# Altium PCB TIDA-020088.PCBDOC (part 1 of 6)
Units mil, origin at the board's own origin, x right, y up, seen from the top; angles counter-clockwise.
Board outline 7520.69 x 5119.11 mil, 6 copper layers (TOP, GND02, SIG03, SIG04, GND05, BOTTOM), stack 87.024 mil thick; 539 components, 269 nets, 1479 pads, 2085 vias.
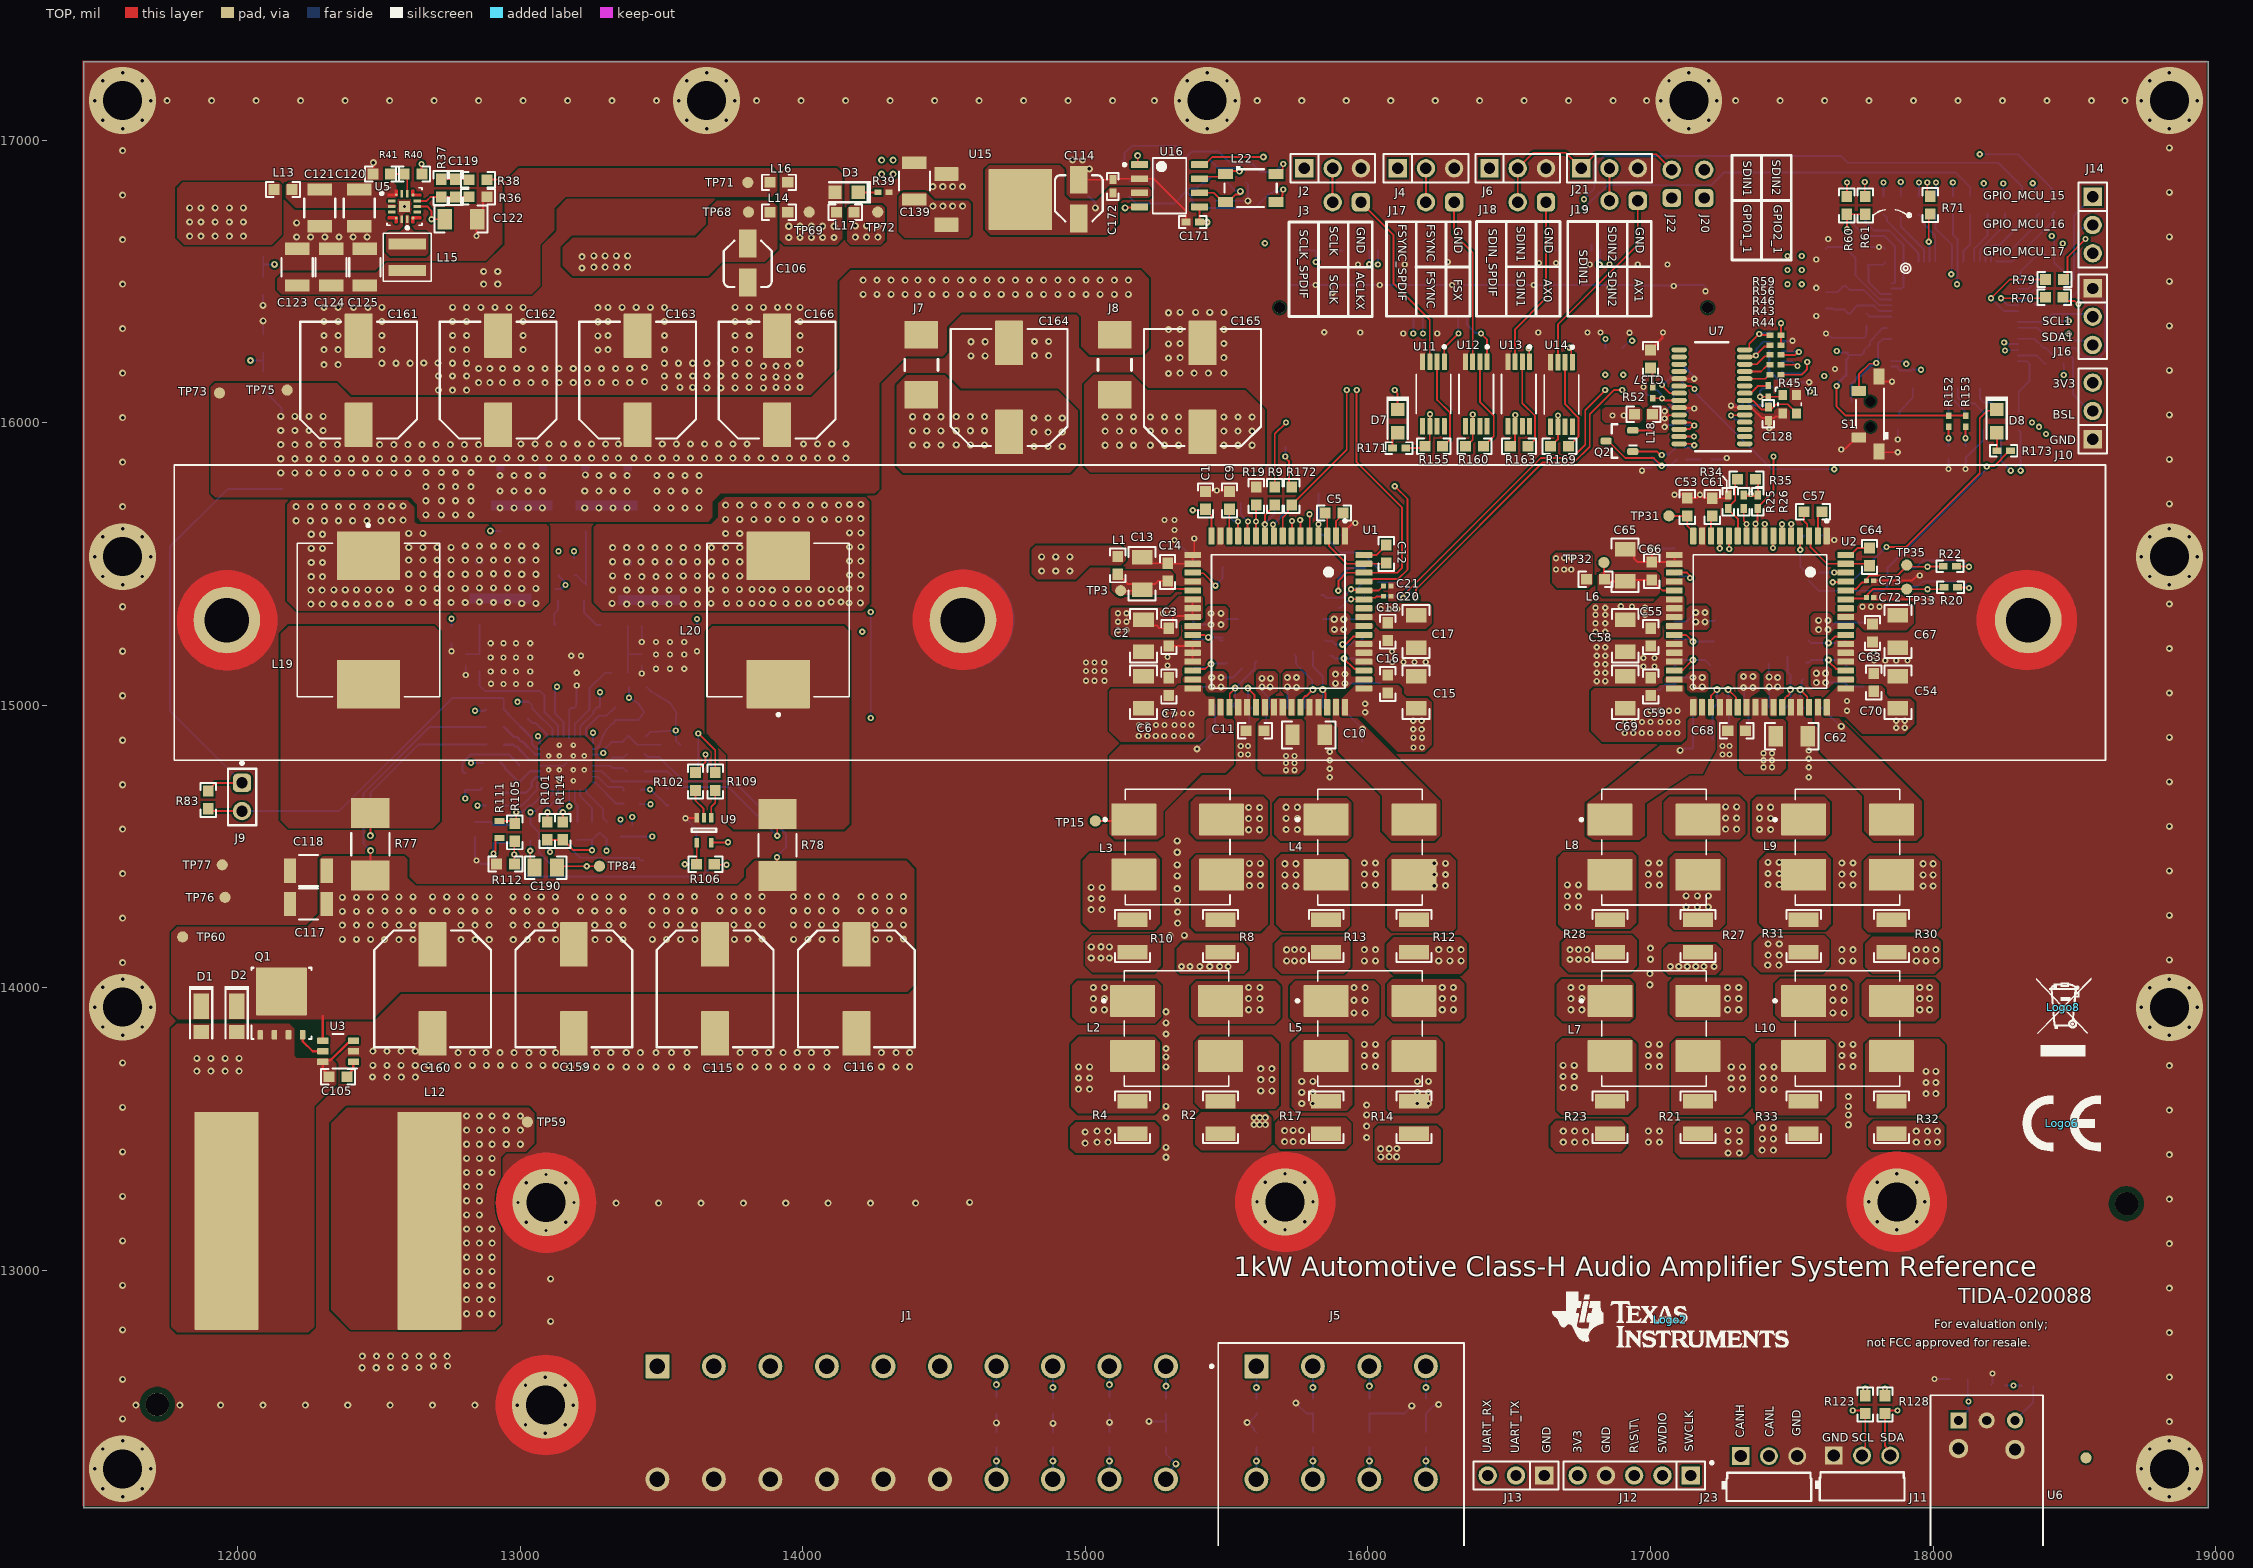
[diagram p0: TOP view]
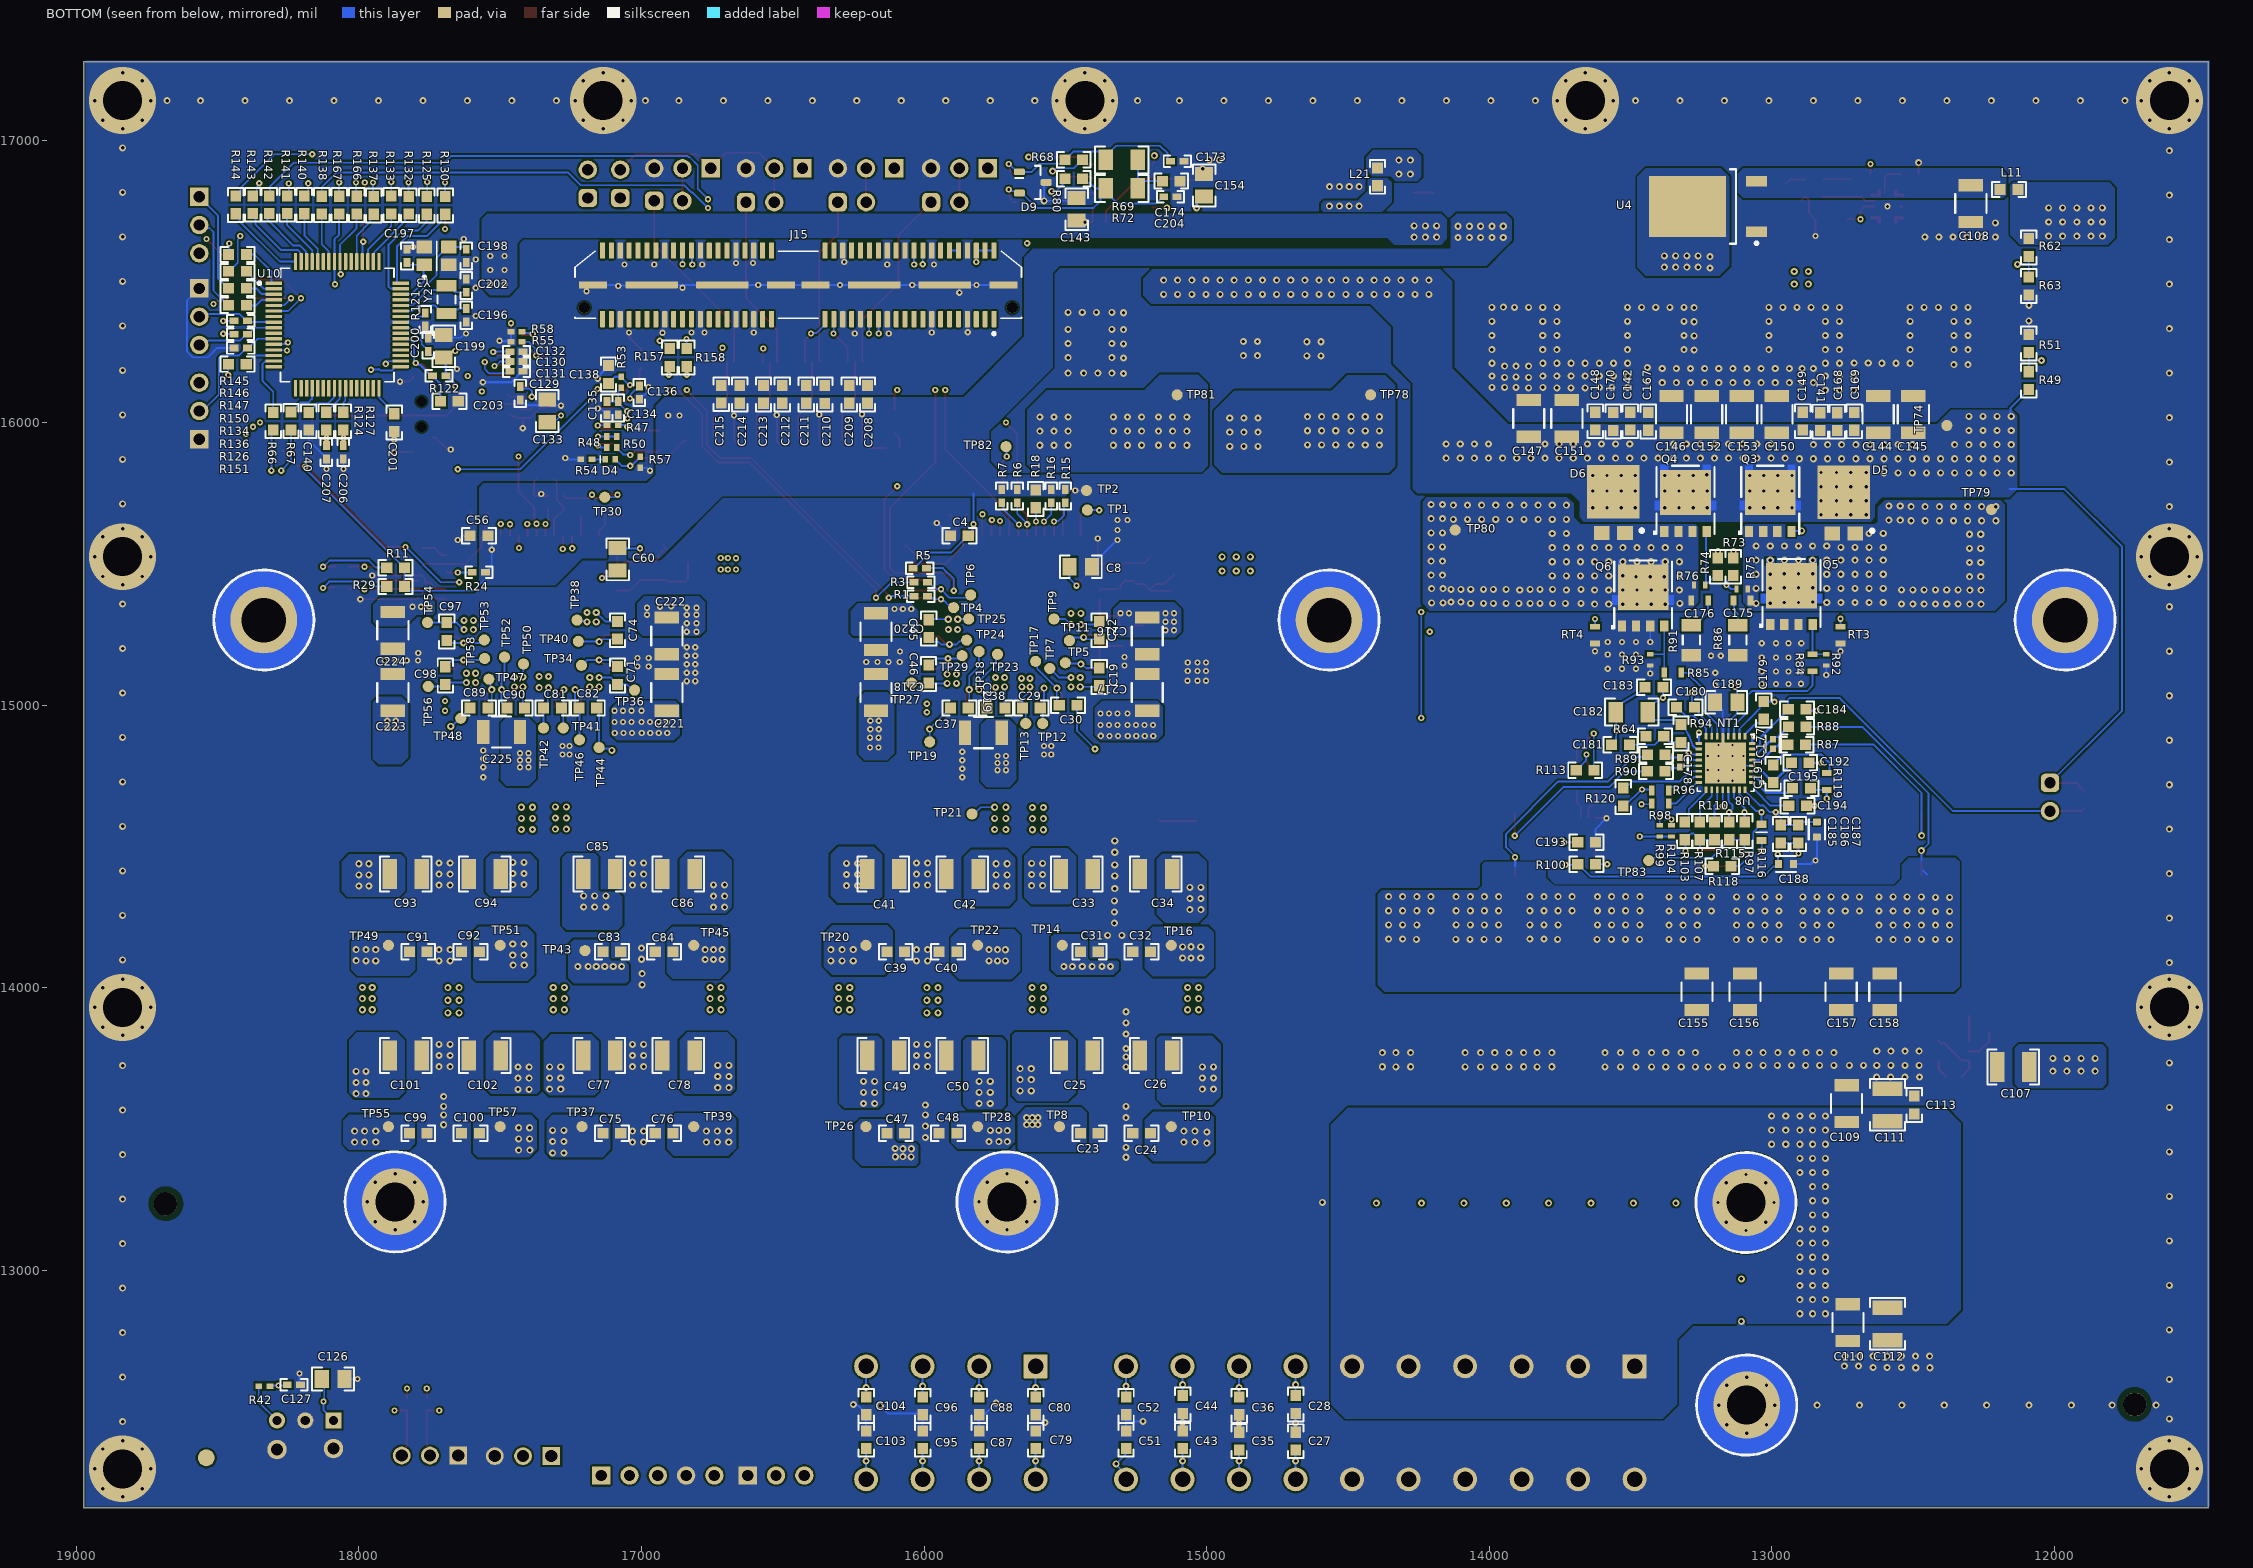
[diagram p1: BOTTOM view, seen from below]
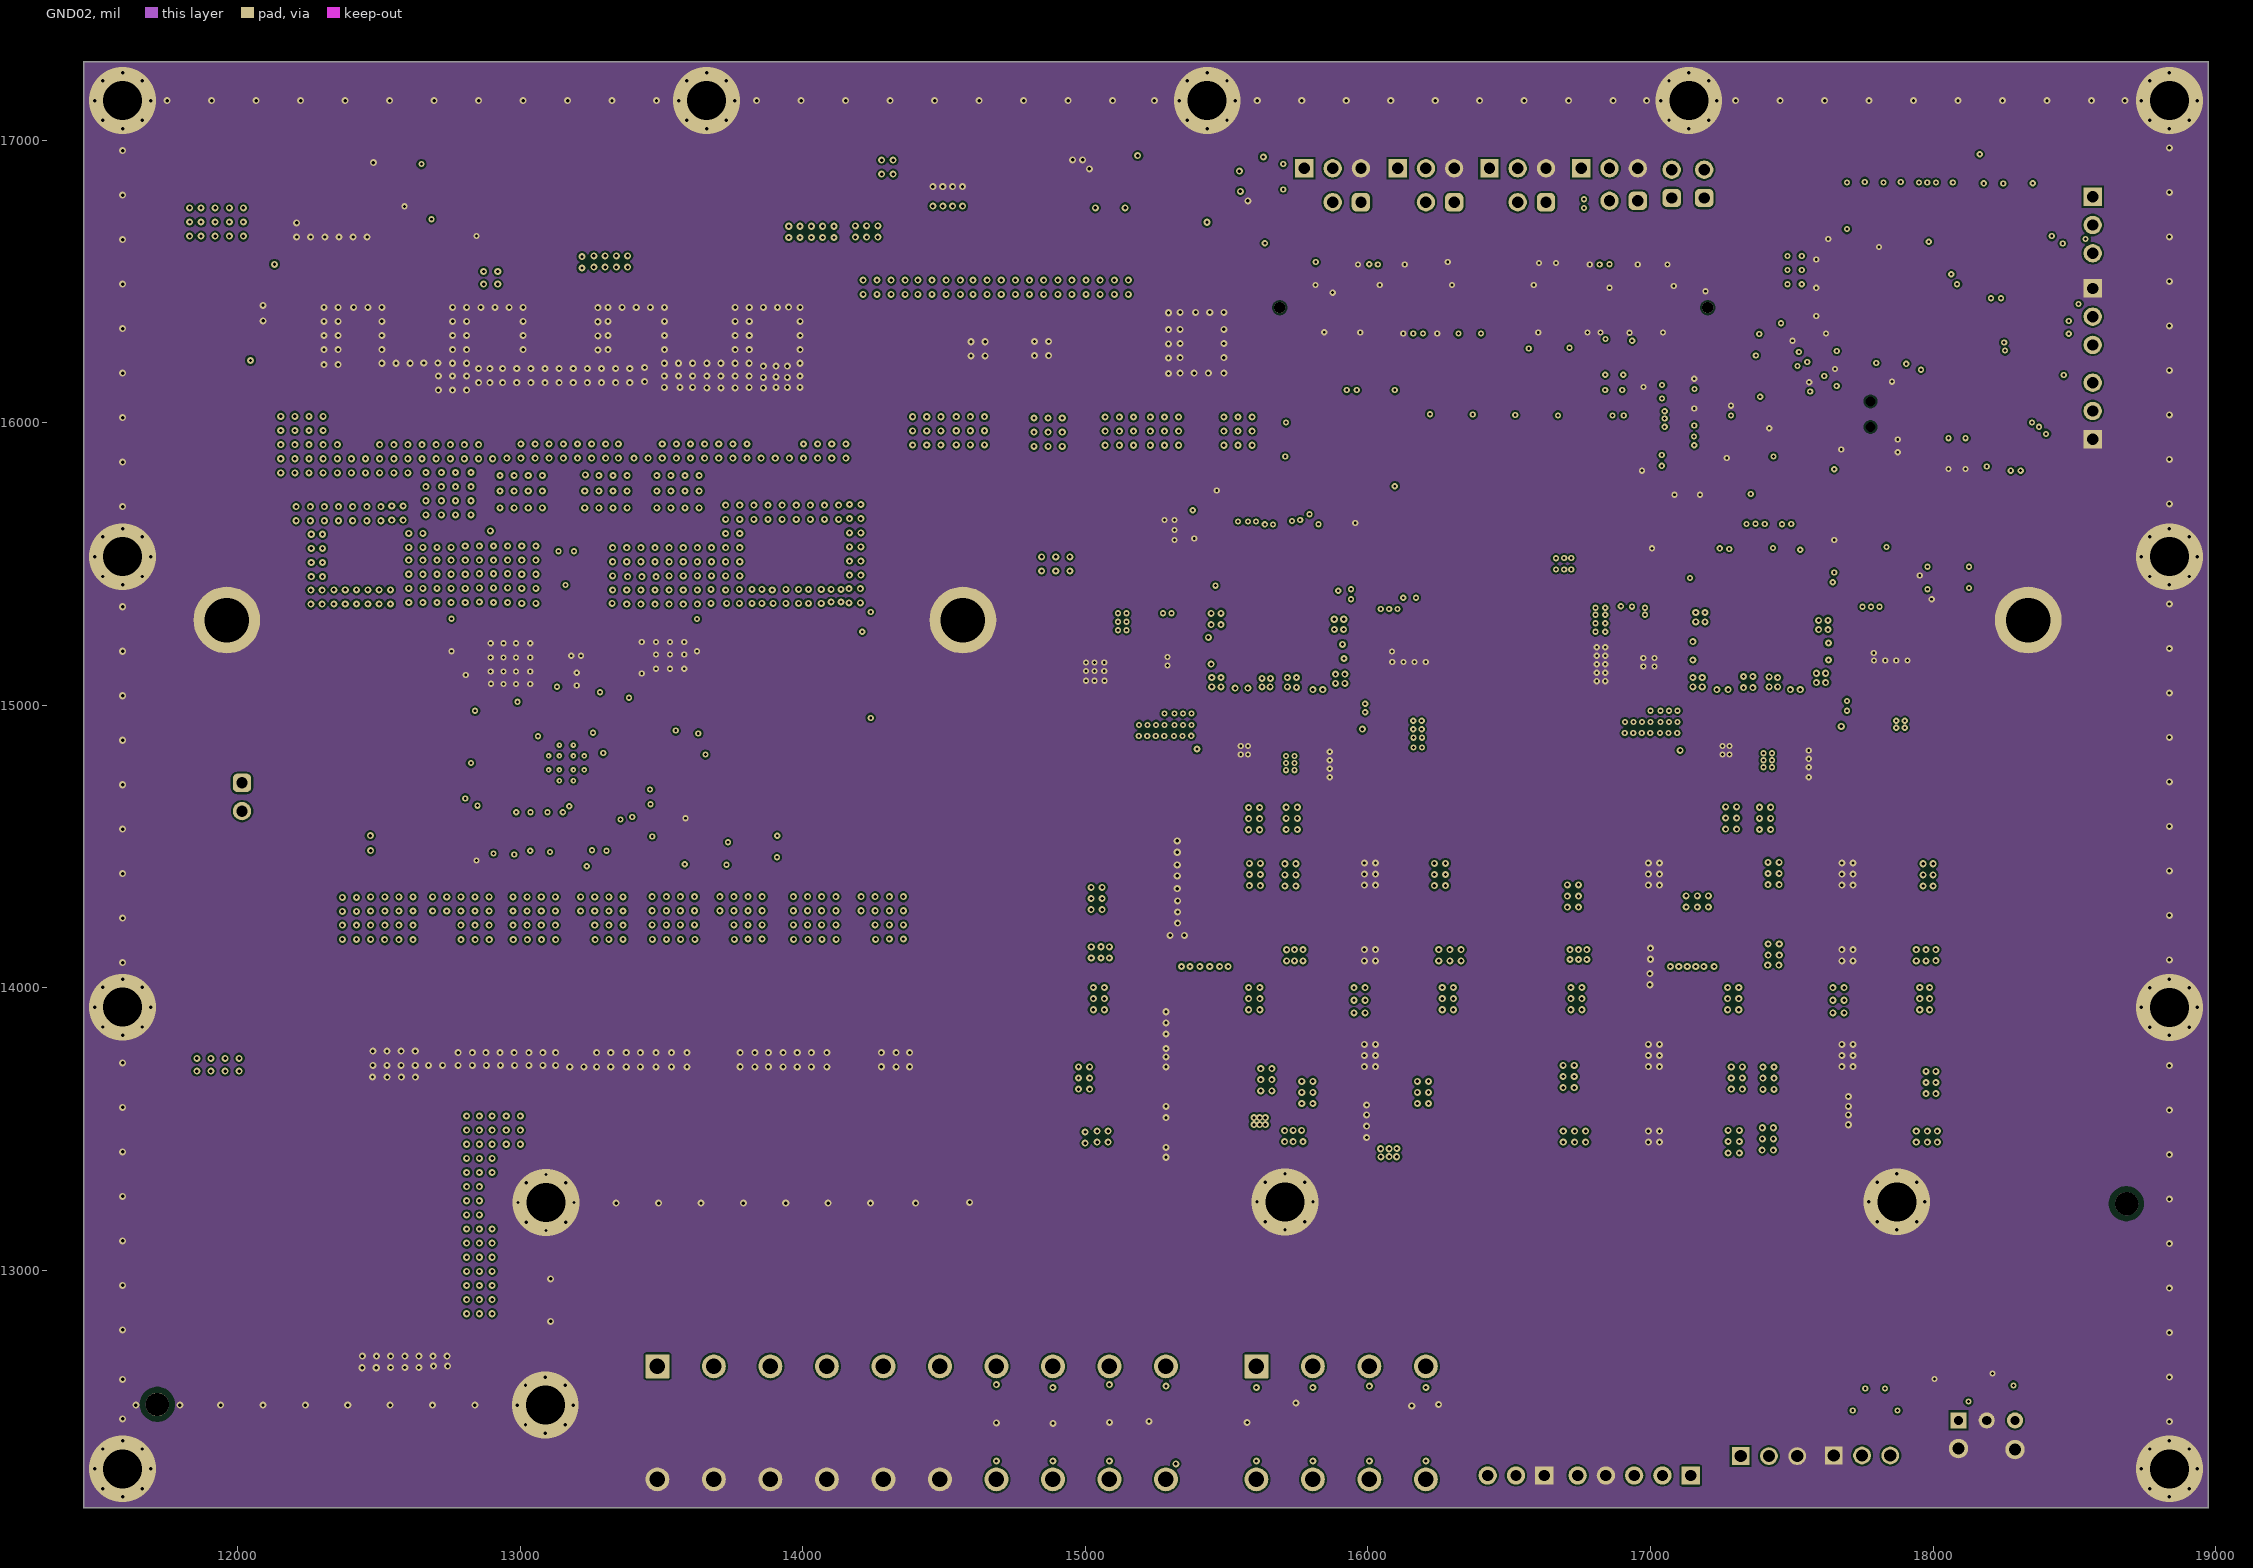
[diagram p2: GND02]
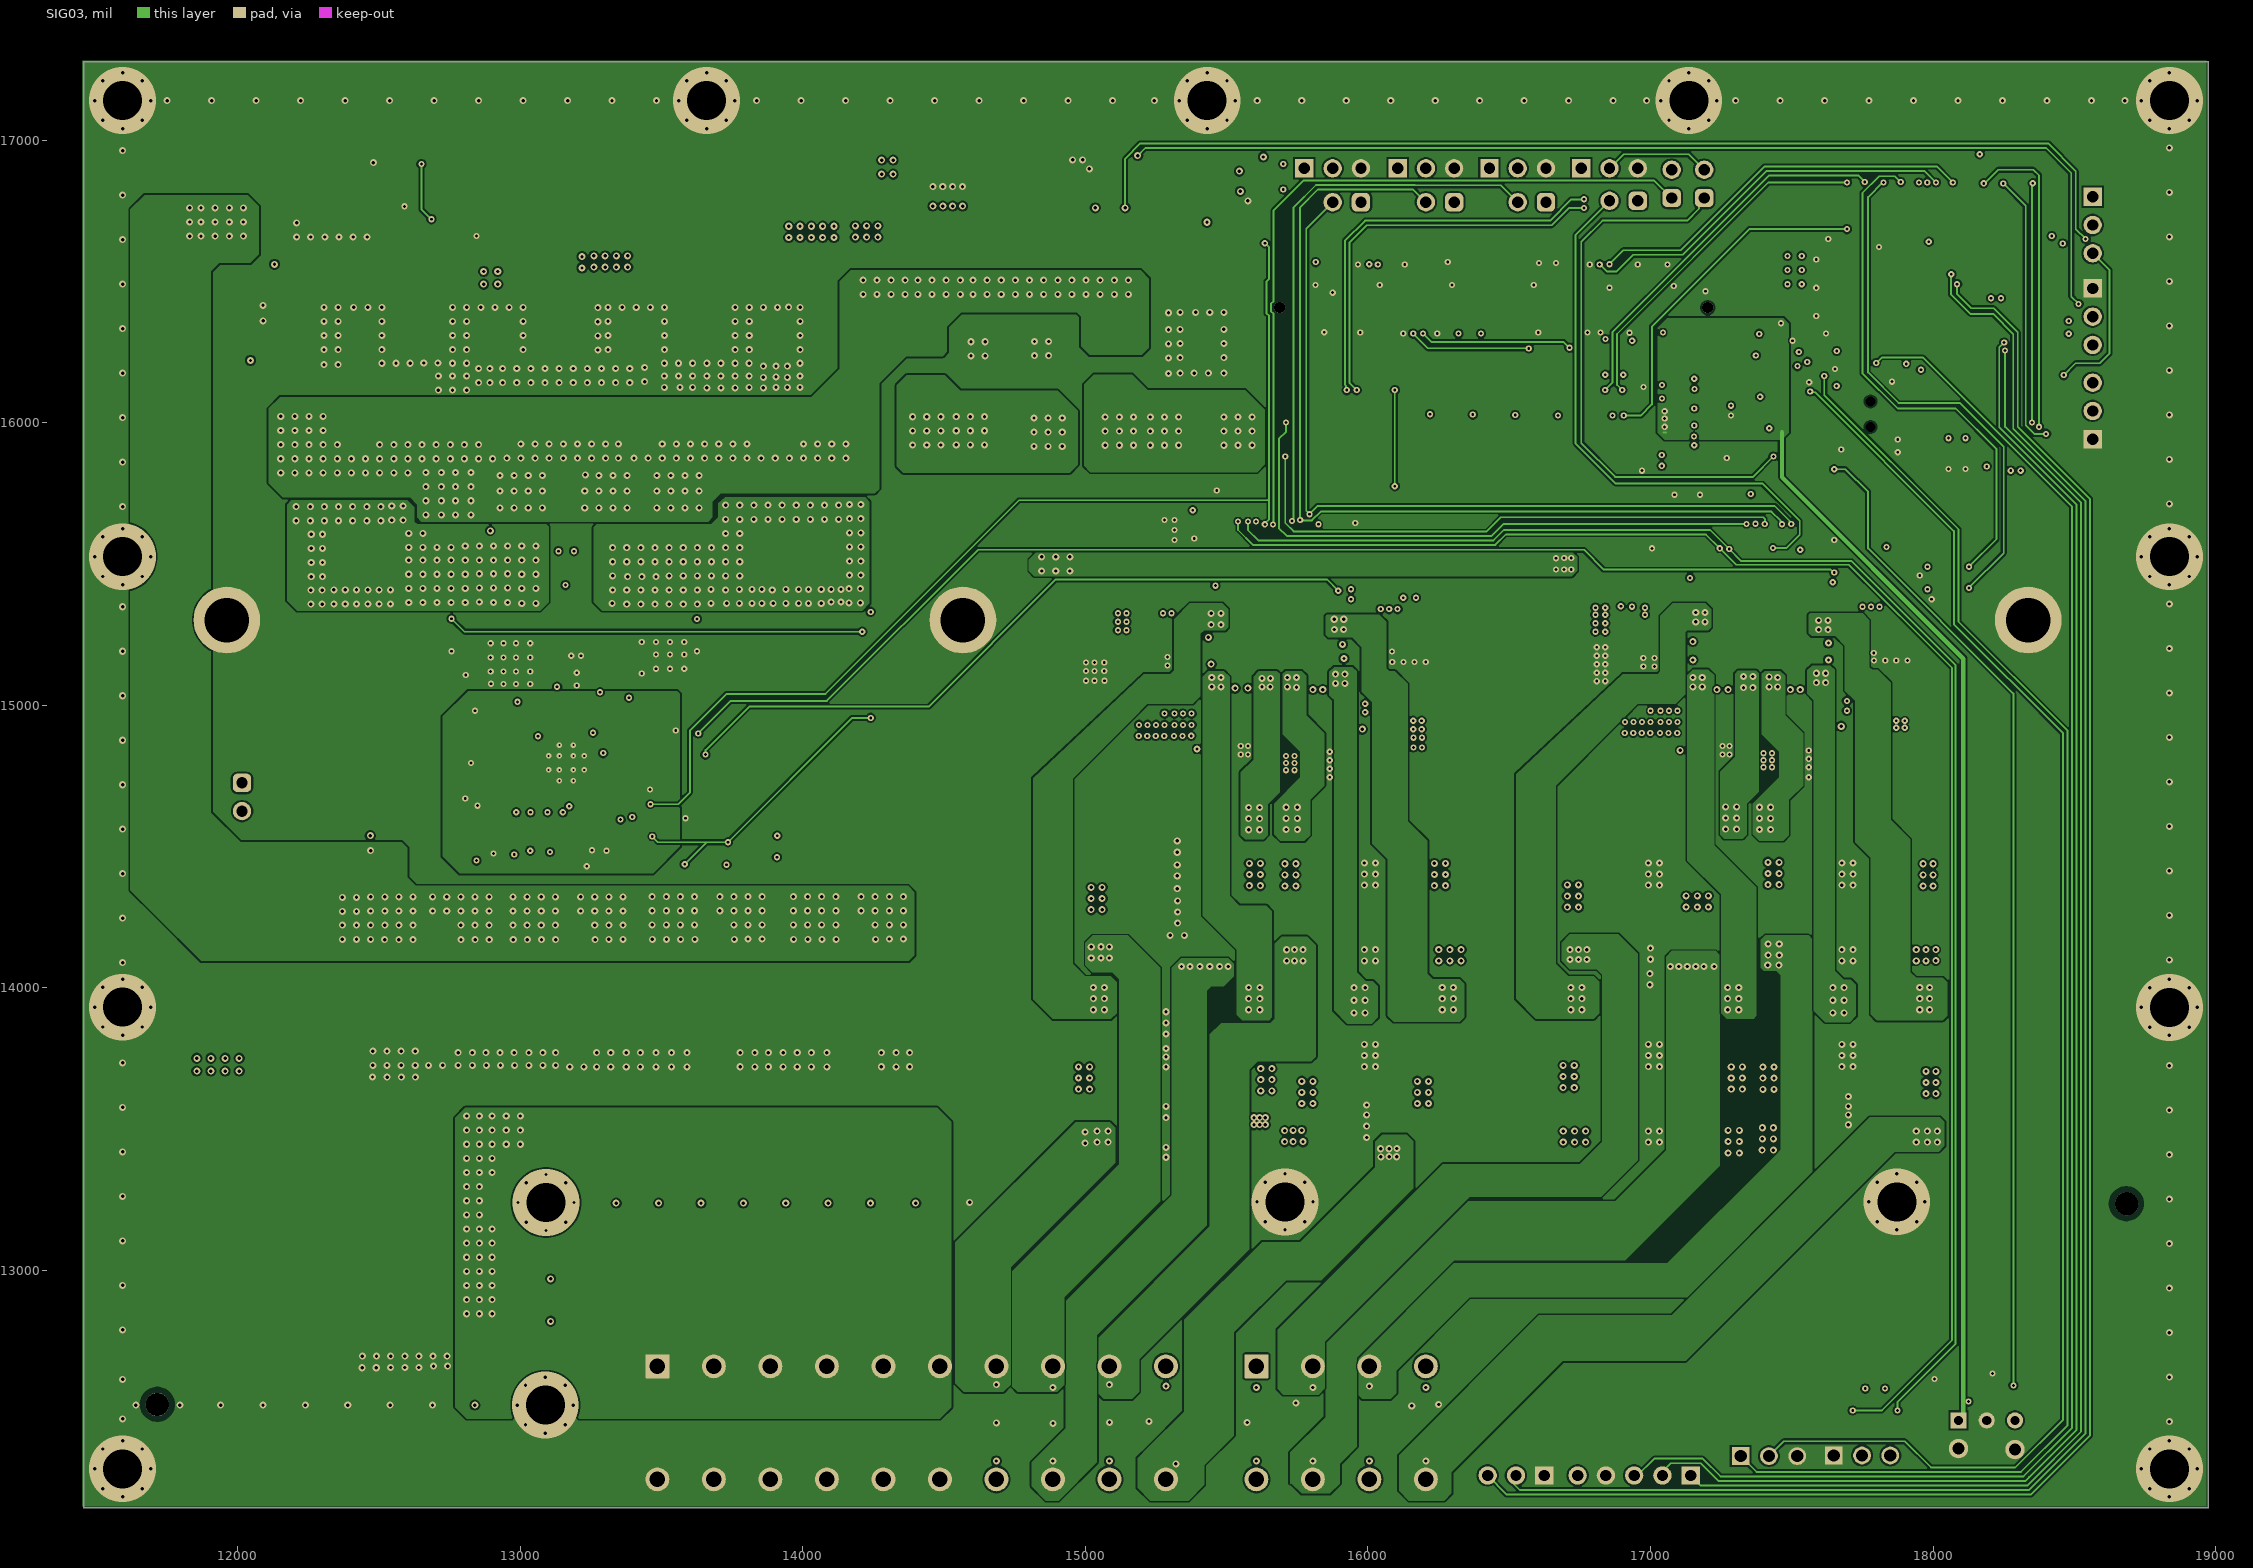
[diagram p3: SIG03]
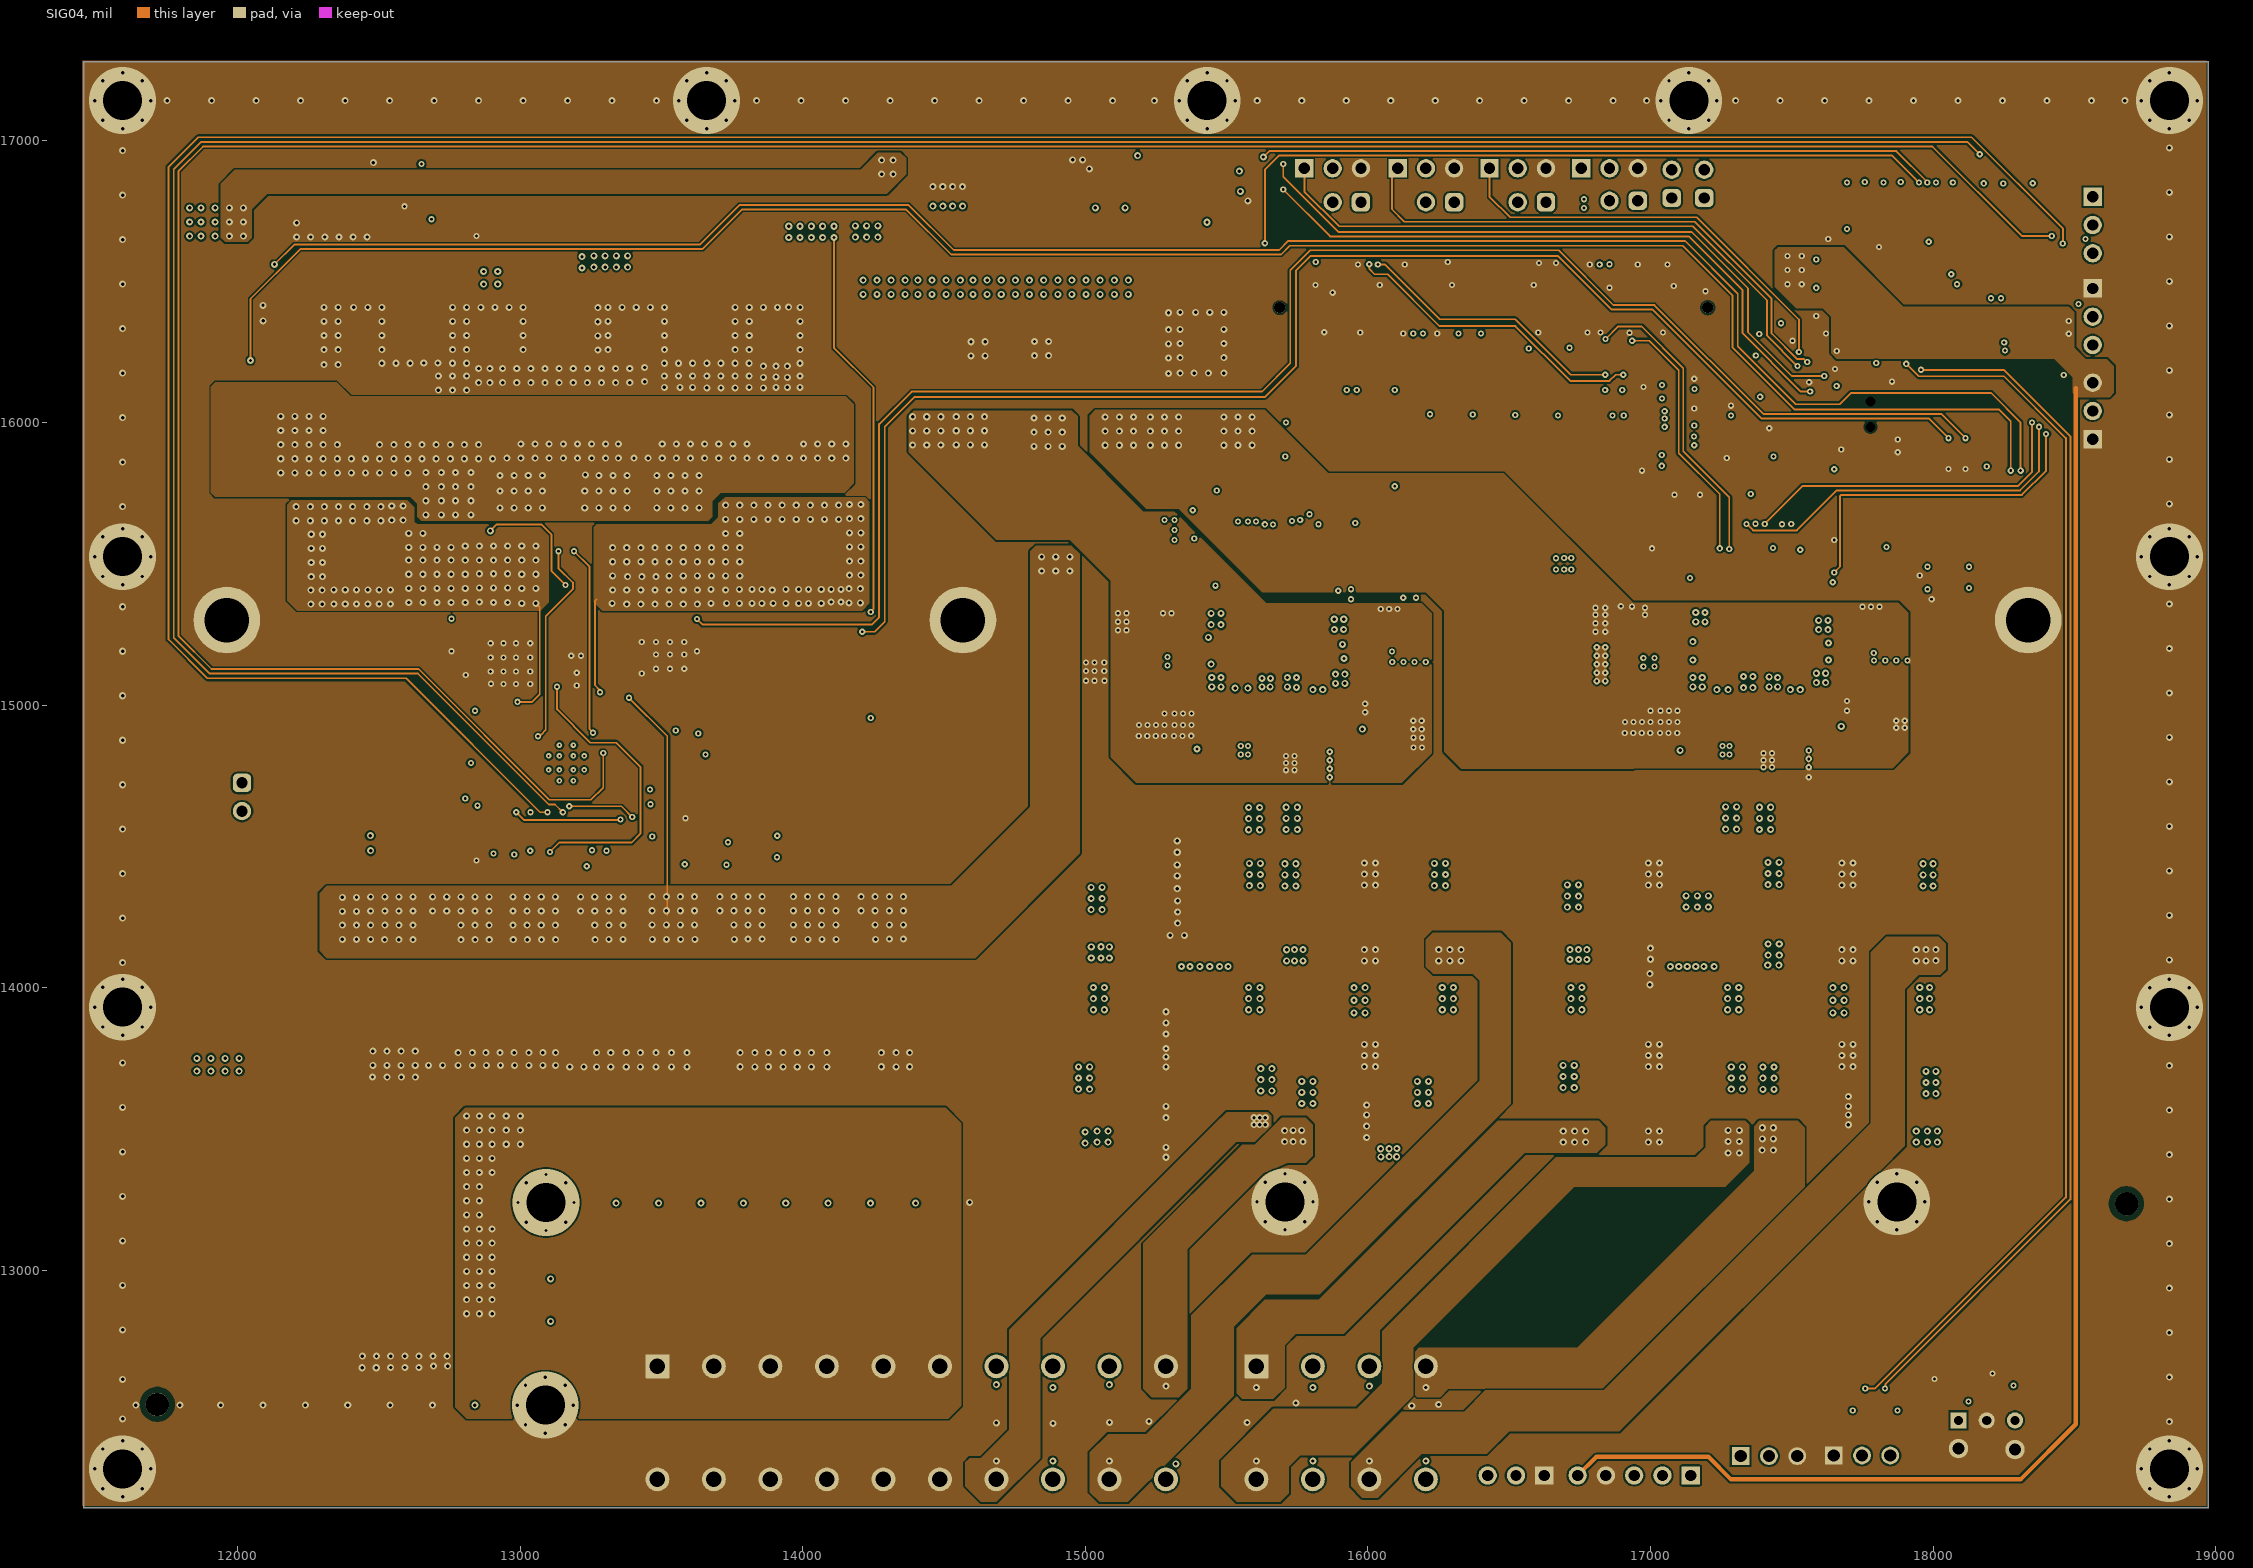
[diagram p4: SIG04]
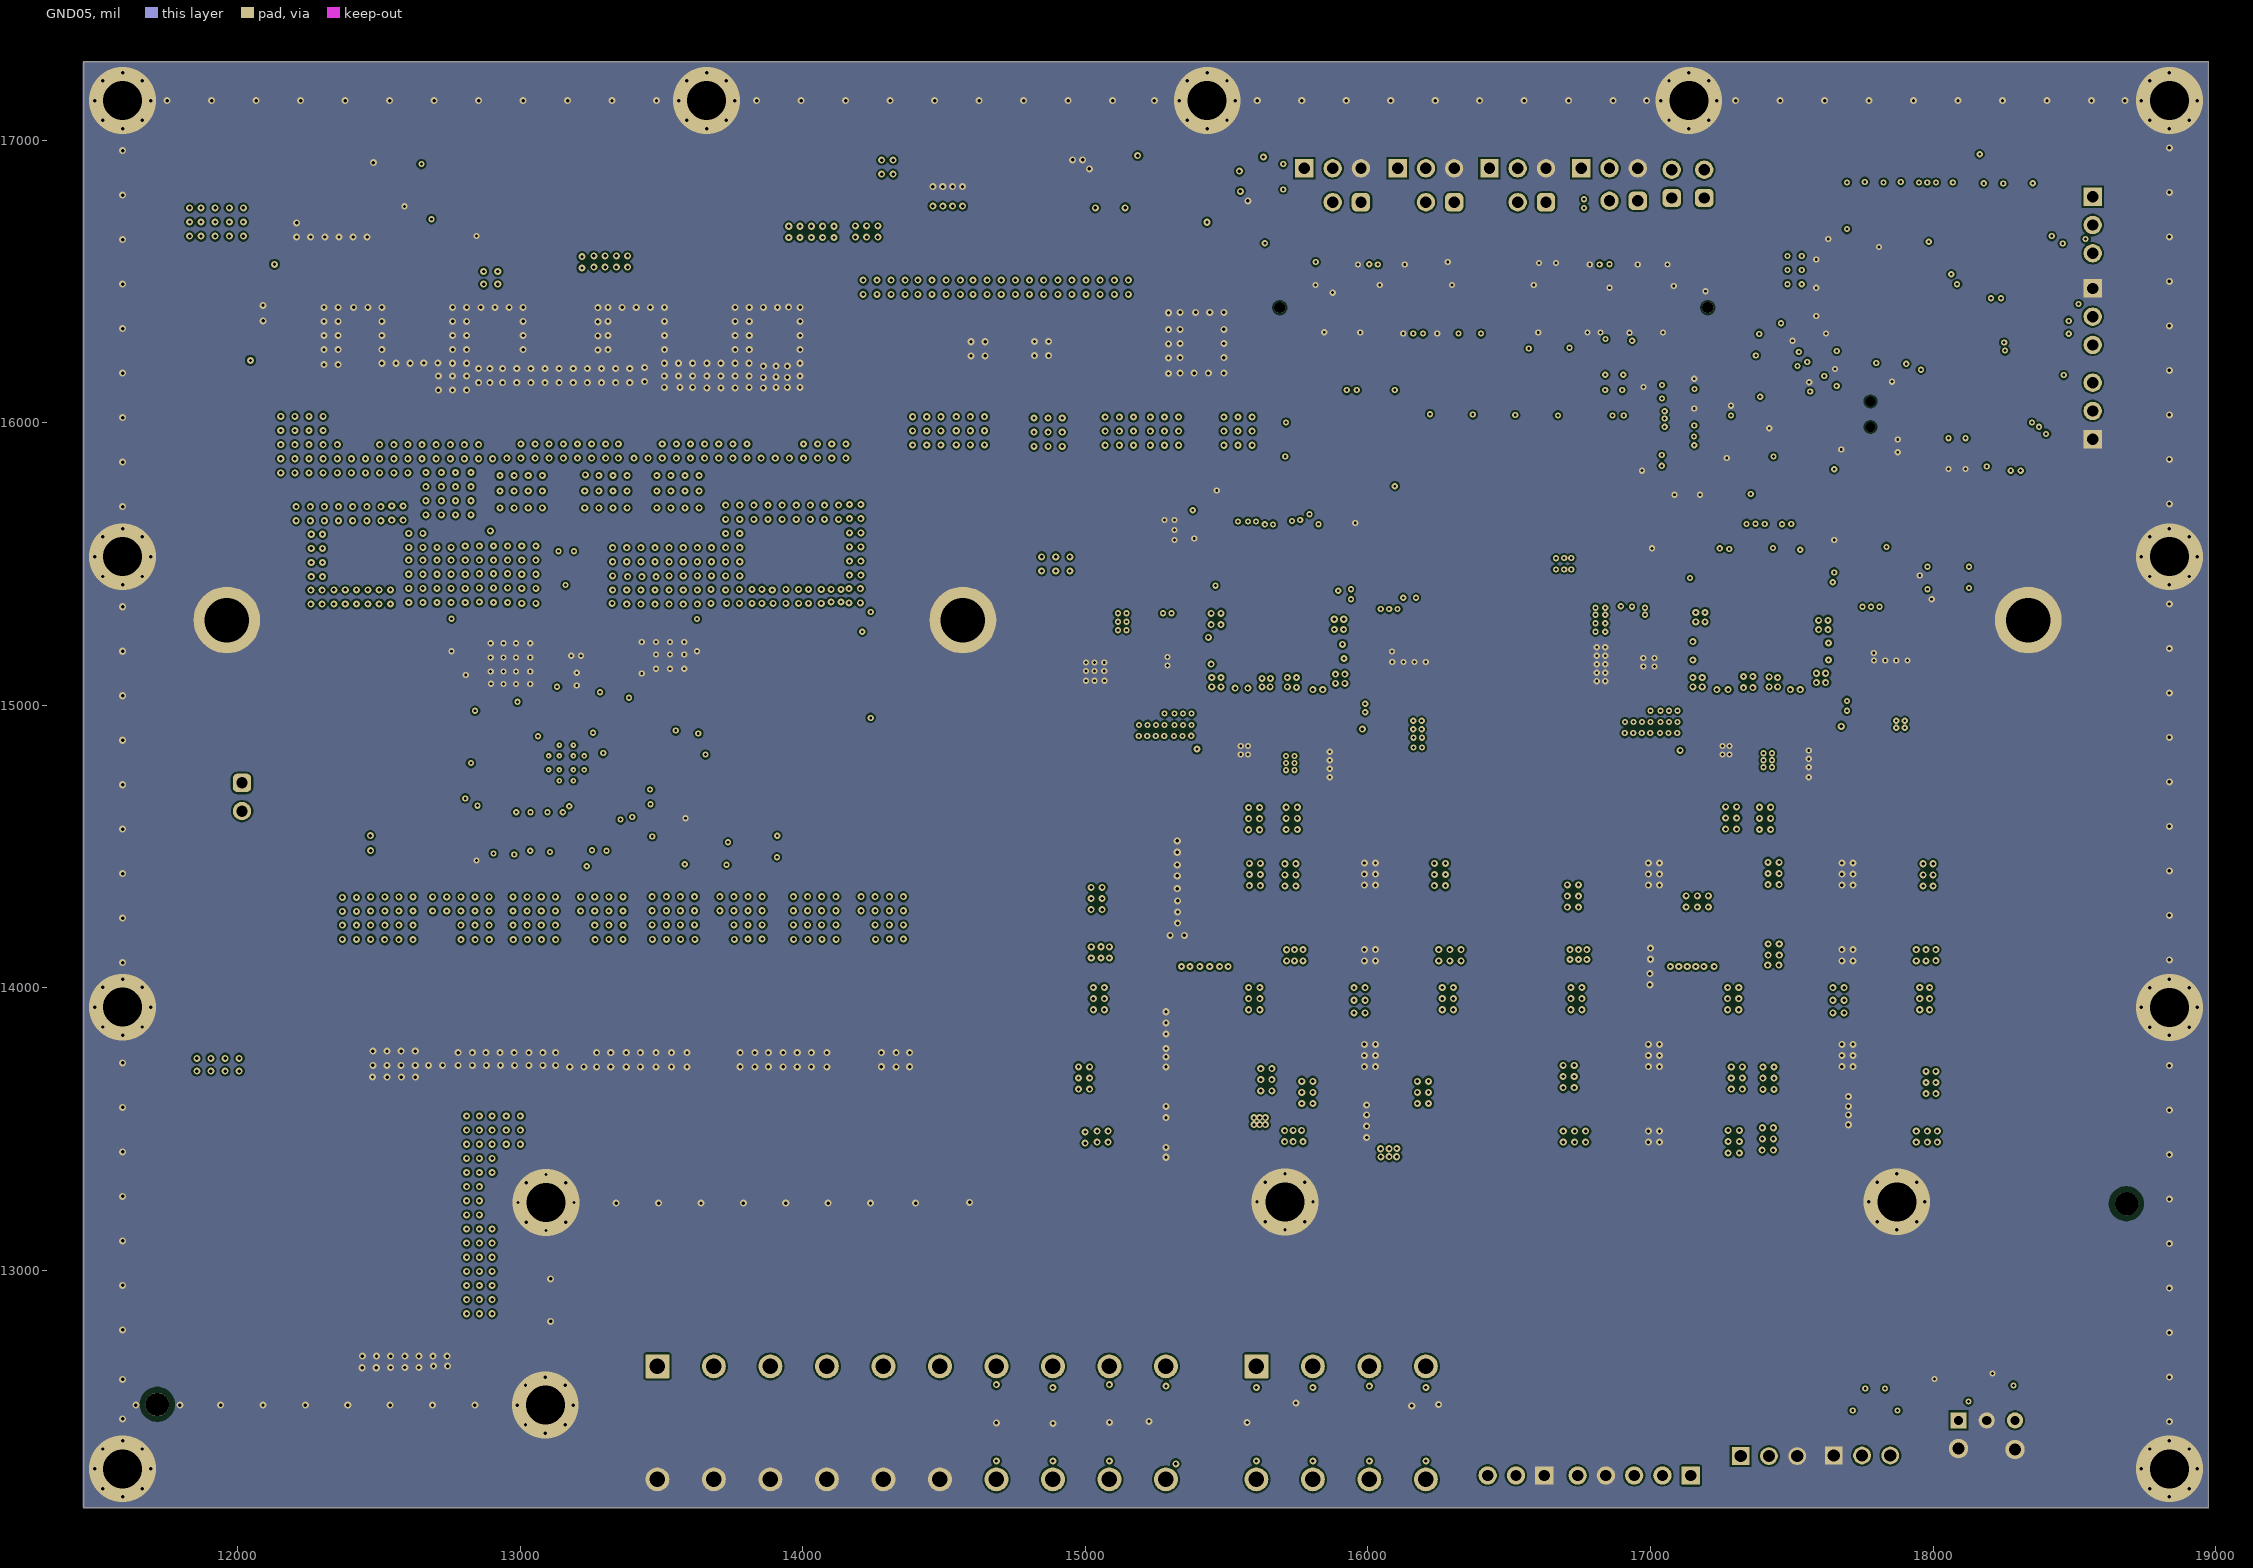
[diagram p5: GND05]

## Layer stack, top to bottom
Top Solder: solder mask 1, SM-002, Dk 4
TOP: signal copper 2.7559
Dielectric1: prepreg 8, FR-4, Dk 4.5
GND02: signal copper 1.378
Dielectric2: core 24, FR-4, Dk 1
SIG03: signal copper 1.378
Dielectric3: prepreg 12, FR-4, Dk 1
SIG04: signal copper 1.378
Dielectric4: core 24, FR-4, Dk 1
GND05: signal copper 1.378
Dielectric5: prepreg 8, FR-4, Dk 1
BOTTOM: signal copper 2.7559
Bottom Solder: solder mask 1, SM-002, Dk 4

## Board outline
11454.06,12159.37 11454.56,12158.87 18974.25,12158.87 18974.75,12159.37 18974.75,17277.48 18974.25,17277.98 11454.56,17277.98 11454.06,17277.48

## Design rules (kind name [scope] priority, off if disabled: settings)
Clearance [All] p1: gap=6.5 ignorepadtopadclearanceinfootprint=FALSE
PlaneConnect [All] p1: planeconnectstyle=Direct reliefexpansion=20 reliefentries=4 reliefconductorwidth=10 reliefairgap=10
PolygonConnect [All] p1: connectstyle=Direct reliefconductorwidth=10 reliefentries=4 polygonreliefangle="90 Angle" airgapwidth=10
RoutingVias [All] p1: holewidth=28 width=50 viastyle="Through Hole" minholewidth=28 minwidth=50 maxholewidth=28 maxwidth=50
SilkToSolderMaskClearance SilkscreenOverComponentPads [IsPad] p1: minsilkscreentomaskgap=10 clearancetoexposedcopper=TRUE
SolderMaskExpansion [All] p1: expansion=4 istentingtop=FALSE
Width [All] p1: maxlimit=100 minlimit=6.5 preferedwidth=8
28 further rules are at their usual default settings.

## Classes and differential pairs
component class Vbat_Input: 0 C105 C106 C107 C108 C109 C110 C111 C112 C113 C114 C115 C116 C117 C118 C119 C120 C121 C122 C123 C124 C125 C139 D1 D2 D3 L11 L12 L13 L14 L15 L16 L17 L21 Q1 R36 R37 R38 R39 R40 R41 TP59 TP60 TP68 TP69 TP71 TP72 U3 U4 U5 U15
component class TAS6684_2: C53 C54 C55 C56 C57 C58 C59 C60 C61 C62 C63 C64 C65 C66 C67 C68 C69 C70 C71 C72 C73 C74 C75 C76 C77 C78 C79 C80 C81 C82 C83 C84 C85 C86 C87 C88 C89 C90 C91 C92 C93 C94 C95 C96 C97 C98 C99 C100 C101 C102 C103 C104 D8 J20 L6 L7 L8 L9 L10 R11 R20 R21 R22 R23 R24 R25 R26 R27 R28 R29 R30 R31 R32 R33 R34 R35 R173 TP30 TP31 TP32 TP33 TP34 TP35 TP36 TP37 TP38 TP39 TP40 TP41 TP42 TP43 TP44 TP45 TP46 TP47 TP48 TP49 TP50 TP51 TP52 TP53 TP54 TP55 TP56 TP57 TP58 U2
component class TAS6684_1: C1 C2 C3 C4 C5 C6 C7 C8 C9 C10 C11 C12 C13 C14 C15 C16 C17 C18 C19 C20 C21 C22 C23 C24 C25 C26 C27 C28 C29 C30 C31 C32 C33 C34 C35 C36 C37 C38 C39 C40 C41 C42 C43 C44 C45 C46 C47 C48 C49 C50 C51 C52 D7 J22 L1 L2 L3 L4 L5 R1 R2 R3 R4 R5 R6 R7 R8 R9 R10 R12 R13 R14 R15 R16 R17 R18 R19 R60 R61 R171 R172 TP1 TP2 TP3 TP4 TP5 TP6 TP7 TP8 TP9 TP10 TP11 TP12 TP13 TP14 TP15 TP16 TP17 TP18 TP19 TP20 TP21 TP22 TP23 TP24 TP25 TP26 TP27 TP28 TP29 TP82 U1
component class "SPDIF and Interface": C126 C127 C128 C129 C130 C131 C132 C133 C134 C135 C136 C137 C138 D4 J1 J2 J4 J5 J6 J21 L18 Logo8 Q2 R42 R43 R44 R45 R46 R47 R48 R50 R52 R53 R54 R55 R56 R57 R58 R59 U6 U7 Y1
component class MCU-MSPM0G3519SPZR: C140 C143 C154 C171 C172 C173 C174 C196 C197 C198 C199 C200 C201 C202 C203 C204 C206 C207 D9 J10 J11 J12 J13 J14 J16 J23 L22 R66 R67 R68 R69 R70 R71 R72 R79 R80 R121 R122 R123 R124 R125 R126 R127 R128 R130 R132 R133 R134 R136 R137 R138 R140 R141 R142 R143 R144 R145 R146 R147 R150 R151 R152 R153 RT3 RT4 S1 U10 U16 Y2 Y3
component class LM5125: C141 C142 C144 C145 C146 C147 C148 C149 C150 C151 C152 C153 C155 C156 C157 C158 C159 C160 C161 C162 C163 C164 C165 C166 C167 C168 C169 C170 C175 C176 C177 C178 C179 C180 C181 C182 C183 C184 C185 C186 C187 C188 C189 C190 C191 C192 C193 C194 C195 C216 C217 C218 C219 C220 C221 C222 C223 C224 C225 D5 D6 J7 J8 J9 L19 L20 NT1 Q3 Q4 Q5 Q6 R49 R51 R62 R63 R64 R73 R74 R75 R76 R77 R78 R83 R84 R85 R86 R87 R88 R89 R90 R91 R92 R93 R94 R96 R97 R98 R99 R100 R101 R102 R103 R104 R105 R106 R107 R109 R110 R111 R112 R113 R114 R115 R116 R118 R119 R120 TP73 TP74 TP75 TP76 TP77 TP78 TP79 TP80 TP81 TP83 TP84 U8 U9
component class Interface_SEM: C208 C209 C210 C211 C212 C213 C214 C215 J3 J15 J17 J18 J19 R155 R157 R158 R160 R163 R166 R167 R169 U11 U12 U13 U14
component class Hardware: !PCB1

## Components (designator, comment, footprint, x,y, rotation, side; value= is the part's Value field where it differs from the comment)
C1 "GCM188R71E105KA64D" 0603 15425,15725 r270 top value=1uF
C2 "GCJ31CR72A105KA01K" 1206 15205.63,15245.64 r270 top value=1uF
C3 "GCJ188R72A104KA01D" 0603 15295.63,15240.64 r90 top value=0.1uF
C4 "GCM188R71E105KA64D" 0603 15875,15600 r180 bottom value=1uF
C5 "GCM188R71E105KA64D" 0603 15880,15680 r0 top value=1uF
C6 "GCJ31CR72A105KA01K" 1206 15205.63,15045.62 r90 top value=1uF
C7 "GCJ188R72A104KA01D" 0603 15295.63,15065.64 r90 top value=0.1uF
C8 "GCM21BR71E225KA73L" 0805_HV 15445,15490 r180 bottom value=2.2uF
C9 "GCM188R71E105KA64D" 0603 15510,15725 r270 top value=1uF
C10 "GCJ31CR72A105KA01K" 1206 15790,14895 r0 top value=1uF
C11 "GCJ188R72A104KA01D" 0603 15600,14910 r180 top value=0.1uF
C12 "GCM188R71E105KA64D" 0603 16065,15535 r90 top value=1uF
C13 "GCJ31CR72A105KA01K" 1206 15200.63,15465.62 r90 top value=1uF
C14 "GCJ188R72A104KA01D" 0603 15290.63,15470.64 r90 top value=0.1uF
C15 "GCJ31CR72A105KA01K" 1206 16170.63,15045.62 r90 top value=1uF
C16 "GCJ188R72A104KA01D" 0603 16070,15075 r90 top value=0.1uF
C17 "GCJ31CR72A105KA01K" 1206 16170.63,15260.64 r270 top value=1uF
C18 "GCJ188R72A104KA01D" 0603 16070,15260 r270 top value=0.1uF
C19 "GCM188R71H224KA64D" 0603 15380,15100 r270 bottom value=0.22uF
C20 "GCM033R71E101KA03D" 0201_033 16067.99,15385 r0 top value=100pF
C21 "GCM033R71E101KA03D" 0201_033 16068.08,15421.8 r0 top value=100pF
C22 "GCM188R71H224KA64D" 0603 15380,15265 r270 bottom value=0.22uF
C23 "DNP" 0603 15415,13485 r180 bottom value=0.22uF
C24 "DNP" 0603 15230,13485 r0 bottom value=0.22uF
C25 "CGA6N3X7R2A225K230AB" 1210_250 15459.37,13760 r180 bottom value=2.2uF
C26 "CGA6N3X7R2A225K230AB" 1210_250 15179.37,13760 r0 bottom value=2.2uF
C27 "CGA3E2X7R2A103K080AA" 0603 14685,12395 r90 bottom value=0.01uF
C28 "CGA3E2X7R2A103K080AA" 0603 14685,12525 r270 bottom value=0.01uF
C29 "GCM188R71H224KA64D" 0603 15620,14990 r0 bottom value=0.22uF
C30 "GCM188R71H224KA64D" 0603 15490,15000 r0 bottom value=0.22uF
C31 "DNP" 0603 15415,14127 r180 bottom value=0.22uF
C32 "DNP" 0603 15230,14127 r0 bottom value=0.22uF
C33 "CGA6N3X7R2A225K230AB" 1210_250 15459.37,14402 r180 bottom value=2.2uF
C34 "CGA6N3X7R2A225K230AB" 1210_250 15179.37,14402 r0 bottom value=2.2uF
C35 "CGA3E2X7R2A103K080AA" 0603 14885,12395 r90 bottom value=0.01uF
C36 "CGA3E2X7R2A103K080AA" 0603 14885,12520 r270 bottom value=0.01uF
C37 "GCM188R71H224KA64D" 0603 15875,14990 r0 bottom value=0.22uF
C38 "GCM188R71H224KA64D" 0603 15745,14990 r0 bottom value=0.22uF
C39 "DNP" 0603 16100,14127 r180 bottom value=0.22uF
C40 "DNP" 0603 15915,14127 r0 bottom value=0.22uF
C41 "CGA6N3X7R2A225K230AB" 1210_250 16144.37,14402 r180 bottom value=2.2uF
C42 "CGA6N3X7R2A225K230AB" 1210_250 15864.37,14402 r0 bottom value=2.2uF
C43 "CGA3E2X7R2A103K080AA" 0603 15085,12400 r90 bottom value=0.01uF
C44 "CGA3E2X7R2A103K080AA" 0603 15085,12525 r270 bottom value=0.01uF
C45 "GCM188R71H224KA64D" 0603 15983.74,15270.78 r90 bottom value=0.22uF
C46 "GCM188R71H224KA64D" 0603 15984,15110 r90 bottom value=0.22uF
C47 "DNP" 0603 16100,13485 r180 bottom value=0.22uF
C48 "DNP" 0603 15915,13485 r0 bottom value=0.22uF
C49 "CGA6N3X7R2A225K230AB" 1210_250 16144.37,13760 r180 bottom value=2.2uF
C50 "CGA6N3X7R2A225K230AB" 1210_250 15864.37,13760 r0 bottom value=2.2uF
C51 "CGA3E2X7R2A103K080AA" 0603 15285,12400 r90 bottom value=0.01uF
C52 "CGA3E2X7R2A103K080AA" 0603 15285,12520 r270 bottom value=0.01uF
C53 "GCM188R71E105KA64D" 0603 17130,15701.5 r270 top value=1uF
C54 "GCJ31CR72A105KA01K" 1206 17875.63,15045.62 r90 top value=1uF
C55 "GCJ188R72A104KA01D" 0603 17000.63,15240.64 r90 top value=0.1uF
C56 "GCM188R71E105KA64D" 0603 17575,15600 r180 bottom value=1uF
C57 "GCM188R71E105KA64D" 0603 17575,15685 r0 top value=1uF
C58 "GCJ31CR72A105KA01K" 1206 16910.63,15245.64 r270 top value=1uF
C59 "GCJ188R72A104KA01D" 0603 17000.63,15065.64 r90 top value=0.1uF
C60 "GCM21BR71E225KA73L" 0805_HV 17084.37,15516.1 r90 bottom value=2.2uF
C61 "GCM188R71E105KA64D" 0603 17218.97,15700.87 r270 top value=1uF
C62 "GCJ31CR72A105KA01K" 1206 17500,14890 r0 top value=1uF
C63 "GCJ188R72A104KA01D" 0603 17785.63,15255.62 r270 top value=0.1uF
C64 "GCM188R71E105KA64D" 0603 17775,15525 r90 top value=1uF
C65 "GCJ31CR72A105KA01K" 1206 16910,15495 r90 top value=1uF
C66 "GCJ188R72A104KA01D" 0603 17005,15475 r90 top value=0.1uF
C67 "GCJ31CR72A105KA01K" 1206 17875.63,15260.64 r270 top value=1uF
C68 "GCJ188R72A104KA01D" 0603 17305,14910 r180 top value=0.1uF
C69 "GCJ31CR72A105KA01K" 1206 16910.63,15045.62 r90 top value=1uF
C70 "GCJ188R72A104KA01D" 0603 17790.63,15080.64 r90 top value=0.1uF
C71 "GCM188R71H224KA64D" 0603 17085,15105 r270 bottom value=0.22uF
C72 "GCM033R71E101KA03D" 0201_033 17777.01,15380.94 r0 top value=100pF
C73 "GCM033R71E101KA03D" 0201_033 17777.01,15440 r0 top value=100pF
C74 "GCM188R71H224KA64D" 0603 17085,15265 r270 bottom value=0.22uF
C75 "DNP" 0603 17105,13485 r180 bottom value=0.22uF
C76 "DNP" 0603 16920,13485 r0 bottom value=0.22uF
C77 "CGA6N3X7R2A225K230AB" 1210_250 17149.37,13760 r180 bottom value=2.2uF
C78 "CGA6N3X7R2A225K230AB" 1210_250 16869.37,13760 r0 bottom value=2.2uF
C79 "CGA3E2X7R2A103K080AA" 0603 15605,12400 r90 bottom value=0.01uF
C80 "CGA3E2X7R2A103K080AA" 0603 15605,12520 r270 bottom value=0.01uF
C81 "GCM188R71H224KA64D" 0603 17315,14990 r0 bottom value=0.22uF
C82 "GCM188R71H224KA64D" 0603 17190,14990 r0 bottom value=0.22uF
C83 "DNP" 0603 17105,14127 r180 bottom value=0.22uF
C84 "DNP" 0603 16920,14127 r0 bottom value=0.22uF
C85 "CGA6N3X7R2A225K230AB" 1210_250 17149.37,14402 r180 bottom value=2.2uF
C86 "CGA6N3X7R2A225K230AB" 1210_250 16869.37,14402 r0 bottom value=2.2uF
C87 "CGA3E2X7R2A103K080AA" 0603 15805,12400 r90 bottom value=0.01uF
C88 "CGA3E2X7R2A103K080AA" 0603 15805,12520 r270 bottom value=0.01uF
C89 "GCM188R71H224KA64D" 0603 17575,14990 r0 bottom value=0.22uF
C90 "GCM188R71H224KA64D" 0603 17445,14990 r0 bottom value=0.22uF
C91 "DNP" 0603 17790,14127 r180 bottom value=0.22uF
C92 "DNP" 0603 17605,14127 r0 bottom value=0.22uF
C93 "CGA6N3X7R2A225K230AB" 1210_250 17834.37,14402 r180 bottom value=2.2uF
C94 "CGA6N3X7R2A225K230AB" 1210_250 17554.37,14402 r0 bottom value=2.2uF
C95 "CGA3E2X7R2A103K080AA" 0603 16005,12400 r90 bottom value=0.01uF
C96 "CGA3E2X7R2A103K080AA" 0603 16005,12520 r270 bottom value=0.01uF
C97 "GCM188R71H224KA64D" 0603 17688.79,15260.66 r90 bottom value=0.22uF
C98 "GCM188R71H224KA64D" 0603 17693.83,15104.36 r90 bottom value=0.22uF
C99 "DNP" 0603 17790,13485 r180 bottom value=0.22uF
C100 "DNP" 0603 17605,13485 r0 bottom value=0.22uF
C101 "CGA6N3X7R2A225K230AB" 1210_250 17834.37,13760 r180 bottom value=2.2uF
C102 "CGA6N3X7R2A225K230AB" 1210_250 17554.37,13760 r0 bottom value=2.2uF
C103 "CGA3E2X7R2A103K080AA" 0603 16205,12400 r90 bottom value=0.01uF
C104 "CGA3E2X7R2A103K080AA" 0603 16205,12520 r270 bottom value=0.01uF
C105 "GCM188R71E105KA64D" 0603 12355,13685 r0 top value=1uF
C106 "EEE-FT1C470AR" Panasonic_B 13805,16565 r270 top value=47uF
C107 "GCM32ER71H475KA55L" 1210_270 12145,13720 r0 bottom value=4.7uF
C108 "UMK325AB7106KMHT" 1210_280 12295,16775 r270 bottom value=10uF
C109 "UMK325AB7106KMHT" 1210_280 12735,13590 r90 bottom value=10uF
C110 "UMK325AB7106KMHT" 1210_280 12730,12815 r270 bottom value=10uF
C111 "GCM32ER71H475KA55L" 1210_270 12590,13585 r90 bottom value=4.7uF
C112 "GCM32ER71H475KA55L" 1210_270 12590,12810 r270 bottom value=4.7uF
C113 "GCJ188R72A104KA01D" 0603 12495,13585 r90 bottom value=0.1uF
C114 "EEE-FT1C470AR" Panasonic_B 14976.56,16790.92 r90 top value=47uF
C115 "UCM1H331MNL1GS" Nichicon_1000x1000 13689.37,13995.63 r270 top value=330uF
C116 "UCM1H331MNL1GS" Nichicon_1000x1000 14189.37,13995.63 r270 top value=330uF
C117 "UMK325AB7106KMHT" 1210_280 12250,14296.26 r180 top value=10uF
C118 "UMK325AB7106KMHT" 1210_280 12250,14414.3 r180 top value=10uF
C119 "GCM1885C2A100JA16D" 0603 12770,16830 r90 top value=10pF
C120 "UMK325AB7106KMHT" 1210_280 12430,16760 r270 top value=10uF
C121 "UMK325AB7106KMHT" 1210_280 12290,16760 r270 top value=10uF
C122 "GCJ31CR72A105KA01K" 1206 12790,16720 r0 top value=1uF
C123 "CGA6P1X7R1C226M250AC" 1210_280 12210,16550 r90 top value=22uF
C124 "CGA6P1X7R1C226M250AC" 1210_280 12330,16550 r90 top value=22uF
C125 "CGA6P1X7R1C226M250AC" 1210_280 12450,16550 r90 top value=22uF
C126 "C0805C106J8RACAUTO" 0805_HV 18091.52,12615 r180 bottom value=10uF
C127 "GCM1555C1H100JA16D" 0402 18230,12595 r180 bottom value=10pF
C128 "GCQ1555C1H200JB01D" 0402 17417.28,16031.37 r270 top value=20pF
C129 "GCQ1555C1H200JB01D" 0402 17428.61,16103.74 r270 bottom value=20pF
C130 "GCM1555C1H100JA16D" 0402 17442.28,16216.37 r180 bottom value=10pF
C131 "GCM1555C1H100JA16D" 0402 17442.28,16181.37 r180 bottom value=10pF
C132 "GCM1555C1H100JA16D" 0402 17442.28,16251.37 r180 bottom value=10pF
C133 "C0805C106J8RACAUTO" 0805_HV 17333.7,16041.37 r90 bottom value=10uF
C134 "GCM155R71C104JA55D" 0402 17082.28,16051.37 r90 bottom value=0.1uF
C135 "GCM155R71C104JA55D" 0402 17122.28,16051.37 r90 bottom value=0.1uF
C136 "GCM155R71H472KA37D" 0402 17007.28,16106.37 r270 bottom value=4700pF
C137 "CGA3E2X7R1H683K080AA" 0603 17000,16225 r90 top value=0.068uF
C138 "GCM188R71E105KA64D" 0603 17116.69,16170.26 r90 bottom value=1uF
C139 "UMK325AB7106KMHT" 1210_280 14395,16855 r90 top value=10uF
C140 "GCM188R71E105KA64D" 0603 18177.66,16004.89 r90 bottom value=1uF
C141 "GCJ188R72A104KA01D" 0603 12828.26,16003.23 r90 bottom value=0.1uF
C142 "GCJ188R72A104KA01D" 0603 13499.98,16005.03 r90 bottom value=0.1uF
C143 "C0805C106J8RACAUTO" 0805_HV 15460,16755 r270 bottom value=10uF
C144 "UMK325AB7106KMHT" 1210_280 12623,16029.38 r90 bottom value=10uF
C145 "UMK325AB7106KMHT" 1210_280 12498.4,16029.38 r90 bottom value=10uF
C146 "UMK325AB7106KMHT" 1210_280 13354.52,16029.38 r90 bottom value=10uF
C147 "UMK325AB7106KMHT" 1210_280 13859.66,16015 r90 bottom value=10uF
C148 "GCJ188R72A104KA01D" 0603 13625,16005 r90 bottom value=0.1uF
C149 "GCJ188R72A104KA01D" 0603 12890.5,16005.03 r90 bottom value=0.1uF
C150 "UMK325AB7106KMHT" 1210_280 12981.37,16029.38 r90 bottom value=10uF
C151 "UMK325AB7106KMHT" 1210_280 13725,16015 r90 bottom value=10uF
C152 "UMK325AB7106KMHT" 1210_280 13230.07,16029.38 r90 bottom value=10uF
C153 "UMK325AB7106KMHT" 1210_280 13106.37,16029.38 r90 bottom value=10uF
C154 "C0805C106J8RACAUTO" 0805_HV 15008.74,16839.7 r270 bottom value=10uF
C155 "UMK325AB7106KMHT" 1210_280 13264.37,13985.62 r270 bottom value=10uF
C156 "UMK325AB7106KMHT" 1210_280 13094.37,13985.62 r270 bottom value=10uF
C157 "UMK325AB7106KMHT" 1210_280 12754.37,13985.62 r270 bottom value=10uF
C158 "UMK325AB7106KMHT" 1210_280 12599.37,13985.62 r270 bottom value=10uF
C159 "UCM1H331MNL1GS" Nichicon_1000x1000 13189.37,13995.63 r270 top value=330uF
C160 "UCM1H331MNL1GS" Nichicon_1000x1000 12689.37,13995.63 r270 top value=330uF
C161 "UCM1H331MNL1GS" Nichicon_1000x1000 12427.52,16150 r90 top value=330uF
C162 "UCM1H331MNL1GS" Nichicon_1000x1000 12921.41,16150 r90 top value=330uF
C163 "UCM1H331MNL1GS" Nichicon_1000x1000 13415.15,16150 r90 top value=330uF
C164 "UCM1H331MNL1GS" Nichicon_1000x1000 14730,16124.37 r90 top value=330uF
C165 "UCM1H331MNL1GS" Nichicon_1000x1000 15414.37,16124.37 r90 top value=330uF
C166 "UCM1H331MNL1GS" Nichicon_1000x1000 13908.89,16150 r90 top value=330uF
C167 "GCJ188R72A104KA01D" 0603 13437.37,16004.32 r90 bottom value=0.1uF
C168 "GCJ188R72A104KA01D" 0603 12768.17,16003.23 r90 bottom value=0.1uF
C169 "GCJ188R72A104KA01D" 0603 12707.73,16004.67 r90 bottom value=0.1uF
C170 "GCJ188R72A104KA01D" 0603 13561.14,16003.96 r90 bottom value=0.1uF
C171 "GCM155R71H104KE02D" 0402 15380,16710 r180 top value=0.1uF
C172 "GCM155R71H104KE02D" 0402 15097.35,16836.24 r90 top value=0.1uF
C173 "GCQ1555C1H200JB01D" 0402 15103.62,16925 r180 bottom value=20pF
C174 "GCM188R71H472KA37D" 0603 15125,16855 r180 bottom value=4700pF
C175 "DNP" 0603S 13105,15370 r0 bottom value=680pF
C176 "DNP" 0603S 13255,15370 r180 bottom value=680pF
C177 "GCM1555C1H680FA16D" FP-GCM155-0_05-IPC_B 12995.11,14862.42 r270 bottom
C178 "GCM1555C1H680FA16D" FP-GCM155-0_05-IPC_B 13324.43,14797.71 r270 bottom
C179 "GCJ188R72A104KA01D" 0603 13028.49,14981.7 r270 bottom value=0.1uF
C180 "GCJ188R72A104KA01D" 0603 13305.2,14992.84 r180 bottom value=0.1uF
C181 "GCJ188R72A104KA01D" 0603 13535,14860 r0 bottom value=0.1uF
C182 "GCJ31CR72A105KA01K" 1206 13495.27,14975.1 r180 bottom value=1uF
C183 "GCJ188R72A104KA01D" 0603 13416.71,15062.78 r0 bottom value=0.1uF
C184 "GCJ188R72A104KA01D" 0603 12910,14985 r180 bottom value=0.1uF
C185 "CGA3E2X7R2A103K080AA" 0603 12967.63,14544.02 r270 bottom value=0.01uF
C186 "CGA3E2X7R2A103K080AA" 0603 12905.8,14544.02 r270 bottom value=0.01uF
C187 "GCJ188R71H473KA12D" FP-GCJ188R71H473KA12D_0603-MFG 12840,14560 r90 bottom
C188 "GCJ188R71H473KA12D" FP-GCJ188R71H473KA12D_0603-MFG 12949.48,14437.77 r0 bottom
C189 "C0805C106J8RACAUTO" 0805_HV 13160.63,15010 r0 bottom value=10uF
C190 "CGA4J1X7R1V335K125AC" 0805_HV 13090,14425 r0 top value=3.3uF
C191 "C0603C153G4GAC7867" 0603 12995.11,14757.2 r90 bottom value=0.015uF
C192 "GCM1885C1H471JA16D" 0603 12898.92,14796 r180 bottom value=470pF
C193 "GCJ188R72A104KA01D" 0603 13655,14515 r180 bottom value=0.1uF
C194 "GCM1885C2A100JA16D" 0603 12908.11,14644.37 r180 bottom value=10pF
C195 "CGA3E3X7R1H334K080AB" 0603 12894.67,14705.65 r180 bottom value=0.33uF
C196 "GCM1555C1H220JA16D" 0402 17620,16380 r90 bottom value=22pF
C197 "GCM1555C1H220JA16D" 0402 17830,16590 r270 bottom value=22pF
C198 "GCM1555C1H220JA16D" 0402 17620,16590 r90 bottom value=22pF
C199 "C0805C106J8RACAUTO" 0805_HV 17700,16270 r270 bottom value=10uF
C200 "GCM155R71H104KE02D" 0402 17755,16275 r90 bottom value=0.1uF
C201 "GCM188R71E474KA64D" 0603 17875,16000 r270 bottom value=0.47uF
C202 "GCM1555C1H220JA16D" 0402 17620,16485 r270 bottom value=22pF
C203 "GCJ188R72A104KA01D" 0603 17680,16075 r180 bottom value=0.1uF
C204 "GCQ1555C1H200JB01D" 0402 15127.99,16799.33 r180 bottom value=20pF
C206 "GCM155R71C104JA55D" 0402 18055,15895 r90 bottom value=0.1uF
C207 "GCM155R71C104JA55D" 0402 18115,15895 r90 bottom value=0.1uF
C208 "GCM188R71E105KA64D" 0603 16200,16100 r270 bottom value=1uF
C209 "GCJ188R72A104KA01D" 0603 16265,16100 r270 bottom value=0.1uF
C210 "GCM188R71E105KA64D" 0603 16351.6,16099.58 r270 bottom value=1uF
C211 "GCJ188R72A104KA01D" 0603 16416.9,16099.92 r270 bottom value=0.1uF
C212 "GCM188R71E105KA64D" 0603 16502.28,16100 r270 bottom value=1uF
C213 "GCJ188R72A104KA01D" 0603 16568.07,16100.07 r270 bottom value=0.1uF
C214 "GCM188R71E105KA64D" 0603 16652.8,16100.07 r270 bottom value=1uF
C215 "GCJ188R72A104KA01D" 0603 16717.53,16100.29 r270 bottom value=0.1uF
C216 "UMK325AB7106KMHT" 1210_280 15210,15245 r270 bottom value=10uF
C217 "UMK325AB7106KMHT" 1210_280 15210,15045 r90 bottom value=10uF
C218 "UMK325AB7106KMHT" 1210_280 16170,15045 r90 bottom value=10uF
C219 "UMK325AB7106KMHT" 1210_280 15790,14903 r0 bottom value=10uF
C220 "UMK325AB7106KMHT" 1210_280 16170,15260 r270 bottom value=10uF
C221 "UMK325AB7106KMHT" 1210_280 16910,15045 r90 bottom value=10uF
C222 "UMK325AB7106KMHT" 1210_280 16910,15245 r270 bottom value=10uF
C223 "UMK325AB7106KMHT" 1210_280 17880,15045 r90 bottom value=10uF
C224 "UMK325AB7106KMHT" 1210_280 17880,15265 r270 bottom value=10uF
C225 "UMK325AB7106KMHT" 1210_280 17495,14905 r0 bottom value=10uF
D1 "FSV360FP" SOD-123HE 11870.08,13899.1 r270 top value=60V
D2 "FSV360FP" SOD-123HE 11995.91,13899.1 r270 top value=60V
D3 "CMP-0002888-1" LTST-C170KGKT_Green 14155,16815 r0 top value=Green
D4 "CMP-0002838-1" LED_SMLP12_BLUE 17110,15870 r0 bottom value=Blue
D5 "V12P10-M3/86A" TO-277A 12745,15680 r0 bottom value=100V
D6 "V12P10-M3/86A" TO-277A 13560,15680.89 r0 bottom value=100V
D7 "LTST-C170KRKT" LED_LTST-C170_Red 16105,16005 r90 top value=Red
D8 "LTST-C170KRKT" LED_LTST-C170_Red 18225,16005 r90 top value=Red
D9 "PESD1CAN,215" SOT-23 15615,16850 r180 bottom value=24V
J1 "1762457" FP-1762457_HDR20-MFG 14385,12305.67 r0 top
J2 "PBC03SAAN" PBC03SAAN 15875,16900 r0 top
J3 "TSW-102-07-G-S" TSW-102-07-G-S 15925,16780 r180 top
J4 "PBC03SAAN" PBC03SAAN 16205,16900 r0 top
J5 "1736713" FP-1736713_HDR8-MFG 15905,12305.67 r0 top
J6 "PBC03SAAN" PBC03SAAN 16530,16900 r0 top
J7 "" HARWIN_S1911-46R 14419.37,16204.37 r270 top
J8 "" HARWIN_S1911-46R 15104.11,16204.37 r270 top
J9 "TSW-102-07-G-S" TSW-102-07-G-S 12015,14675 r270 top
J10 "PBC03SAAN" PBC03SAAN 18565,16041.26 r90 top
J11 "61300311021" Wurth_61300311021 17748.64,12344.37 r0 top
J12 "HTSW-105-07-G-S" Samtec_HTSW-105-07-G-S 16942.07,12273.75 r180 top
J13 "PBC03SAAN" PBC03SAAN 16523.69,12273.75 r180 top
J14 "PBC03SAAN" PBC03SAAN 18565,16699.37 r270 top
J15 "QTE-040-01-L-D-A" FP-QTE-040-01-L-D-A_HDR80-MFG 16445.19,16487.46 r0 bottom
J16 "PBC03SAAN" PBC03SAAN 18565,16375 r270 top
J17 "TSW-102-07-G-S" TSW-102-07-G-S 16255,16780 r180 top
J18 "TSW-102-07-G-S" TSW-102-07-G-S 16580,16780 r180 top
J19 "TSW-102-07-G-S" TSW-102-07-G-S 16905,16785 r180 top
J20 "TSW-102-07-G-S" TSW-102-07-G-S 17190,16845 r90 top
J21 "PBC03SAAN" PBC03SAAN 16855,16900 r0 top
J22 "TSW-102-07-G-S" TSW-102-07-G-S 17075,16845 r90 top
J23 "61300311021" Wurth_61300311021 17419.17,12342.19 r0 top
L1 "BLM18SG121TZ1D" 0603 15115,15495 r270 top
L2 "VAMV1009AA-100MM2" FP-VAMV1009AA-100MM2_SMT_CMC_9MM2_10MM2-MFG 15322.52,13855.63 r0 top
L3 "VAMV1009AA-100MM2" FP-VAMV1009AA-100MM2_SMT_CMC_9MM2_10MM2-MFG 15326.46,14497.81 r0 top
L4 "VAMV1009AA-100MM2" FP-VAMV1009AA-100MM2_SMT_CMC_9MM2_10MM2-MFG 16007.52,14497.63 r0 top
L5 "VAMV1009AA-100MM2" FP-VAMV1009AA-100MM2_SMT_CMC_9MM2_10MM2-MFG 16007.52,13855.63 r0 top
L6 "BLM18SG121TZ1D" 0603 16805,15445 r0 top
L7 "VAMV1009AA-100MM2" FP-VAMV1009AA-100MM2_SMT_CMC_9MM2_10MM2-MFG 17012.52,13855.63 r0 top
L8 "VAMV1009AA-100MM2" FP-VAMV1009AA-100MM2_SMT_CMC_9MM2_10MM2-MFG 17012.52,14497.63 r0 top
L9 "VAMV1009AA-100MM2" FP-VAMV1009AA-100MM2_SMT_CMC_9MM2_10MM2-MFG 17697.52,14497.63 r0 top
L10 "VAMV1009AA-100MM2" FP-VAMV1009AA-100MM2_SMT_CMC_9MM2_10MM2-MFG 17697.52,13855.63 r0 top
L11 "DNP" 0603 12160,16825 r0 bottom
L12 "SRP2313AA-1R0M" SRP2313AA 12319.25,13175 r180 top locked value=1uH
L13 "BLM18SG121TZ1D" 0603 12160,16825 r0 top
L14 "DNP" 0603 13915,16745 r0 top
L15 "XEL4030-222MEC" FP-XEL4030-222MEC_SMT2_4MM0_4MM0-MFG 12600,16585 r270 top value=2.2uH
L16 "BLM18SG121TZ1D" 0603 13915,16850 r0 top
L17 "BLM18SG121TZ1D" 0603 14150,16745 r0 top
L18 "BLM18SG121TZ1D" 0603 16975,16030 r180 top
L19 "VCMV136E-3R3MN2" FP-VCMV136E-3R3MN2_SMT_IND_13MM45_12MM6-MFG 12462.52,15301.37 r270 top locked value=3.3uH
L20 "VCMV136E-3R3MN2" FP-VCMV136E-3R3MN2_SMT_IND_13MM45_12MM6-MFG 13912.52,15301.37 r90 top locked value=3.3uH
L21 "BLM18SG121TZ1D" 0603 14395,16870 r270 bottom
L22 "ACT45B-101-2P-TL003" ACT45B 15585,16830 r0 top value=100uH
Logo2 "Texas Instruments" TI_Stacked_Overlay_Small 17070,12825 r0 top
Logo6 "CE Mark" CE_Mark_5mm 18455,13520 r0 top
Logo7 "FCC disclaimer" FCC_disclaimer_stacked 21945,16640 r0 top
Logo8 "WEEE logo" WEEE_Minimum 18460,13930 r0 top
NT1 "Net-Tie" Net-Tie_10milWide_30milLong 13172.59,14867.69 r90 bottom net-tie
Q1 "CSD16570Q5B" DNK0008A 12154.41,13944.45 r90 top value=25V
Q2 "MMBT3906" SOT-23 16890,15935 r180 top value="40 V"
Q3 "NTM" SO-8FL 13005,15725.04 r90 bottom value=60V
Q4 "NTM" SO-8FL 13305,15725.04 r90 bottom value=60V
Q5 "NTM" SO-8FL 12930,15395.04 r90 bottom value=60V
Q6 "NTM" SO-8FL 13455,15390 r90 bottom value=60V
R1 "CRCW040210K0FKED" 0402 16011.59,15385.87 r0 bottom value=10.0k
R2 "CRCW12100000Z0EAHP" 1210 15477.83,13541 r270 top value=0
R3 "CRCW040210K0FKED" 0402 16011.38,15435 r180 bottom value=10.0k
R4 "CRCW12100000Z0EAHP" 1210 15167.2,13541 r270 top value=0
R5 "CRCW04022K20FKED" 0402 16015,15485 r0 bottom value=2.20k
R6 "CRCW040210K0FKED" 0402 15670,15740 r90 bottom value=10.0k
R7 "DNP" 0402 15725,15740 r90 bottom value=10.0k
R8 "CRCW12100000Z0EAHP" 1210 15477.83,14183 r270 top value=0
R9 "DNP" 0603 15670,15740 r90 top value=0
R10 "CRCW12100000Z0EAHP" 1210 15167.2,14183 r270 top value=0
R11 "CRCW06030000Z0EA" 0603 17870.02,15486.7 r180 bottom value=0
R12 "CRCW12100000Z0EAHP" 1210 16162.83,14183 r270 top value=0
R13 "CRCW12100000Z0EAHP" 1210 15852.2,14183 r270 top value=0
R14 "CRCW12100000Z0EAHP" 1210 16162.83,13541 r270 top value=0
R15 "CRCW04022K20FKED" 0402 15500,15740 r90 bottom value=2.20k
R16 "CRCW04022K20FKED" 0402 15550,15740 r90 bottom value=2.20k
R17 "CRCW12100000Z0EAHP" 1210 15852.2,13541 r270 top value=0
R18 "DNP" 0603 15605,15730 r270 bottom value=0
R19 "CRCW06030000Z0EA" 0603 15605,15740 r90 top value=0
R20 "CRCW040210K0FKED" 0402 18062.2,15417.26 r0 top value=10.0k
R21 "CRCW12100000Z0EAHP" 1210 17167.83,13541 r270 top value=0
R22 "CRCW040210K0FKED" 0402 18059.85,15491.32 r180 top value=10.0k
R23 "CRCW12100000Z0EAHP" 1210 16857.2,13541 r270 top value=0
R24 "CRCW04022K20FKED" 0402 17575.48,15470 r180 bottom value=2.20k
R25 "CRCW040210K0FKED" 0402 17330,15720 r90 top value=10.0k
R26 "DNP" 0402 17380,15720 r90 top value=10.0k
R27 "CRCW12100000Z0EAHP" 1210 17167.83,14183 r270 top value=0
R28 "CRCW12100000Z0EAHP" 1210 16857.2,14183 r270 top value=0
R29 "CRCW06030000Z0EA" 0603 17870,15420 r180 bottom value=0
R30 "CRCW12100000Z0EAHP" 1210 17852.83,14183 r270 top value=0
R31 "CRCW12100000Z0EAHP" 1210 17542.2,14183 r270 top value=0
R32 "CRCW12100000Z0EAHP" 1210 17852.83,13541 r270 top value=0
R33 "CRCW12100000Z0EAHP" 1210 17542.2,13541 r270 top value=0
R34 "CRCW04021K00JNED" 0402 17275,15720 r90 top value=1.0k
R35 "DNP" 0603 17340,15800 r180 top value=0
R36 "DNP" 0603 12850,16800 r0 top value=0
R37 "CRCW06030000Z0EA" 0603 12720,16830 r90 top value=0
R38 "CRCW06030000Z0EA" 0603 12850,16860 r0 top value=0
R39 "CRCW04021K00JNED" 0402L 14285.32,16815 r180 top value=1.0k
R40 "DNP" 0603 12620,16880 r180 top value=0
R41 "CRCW06030000Z0EA" 0603 12510,16880 r0 top value=0
R42 "CMP-0026404-2" 0402L 18334.69,12590 r180 bottom value=49.9
R43 "CMP-0026404-2" 0402L 17442.28,16204.56 r0 top value=49.9
R44 "CMP-0026404-2" 0402L 17442.28,16169.56 r0 top value=49.9
R45 "CRCW0402470RJNED" 0402L 17417.28,16111.37 r90 top value=470
R46 "CMP-0026404-2" 0402L 17442.28,16239.56 r0 top value=49.9
R47 "CMP-0026414-2" 0402L 17102.28,15991.37 r180 bottom value=4.99k
R48 "CMP-0026404-2" 0402L 17122.28,15931.37 r90 bottom value=49.9
R49 "CRCW0603560KFKEA" 0603 12090,16148.5 r90 bottom value=560k
R50 "CMP-0026414-2" 0402L 17087.28,15931.37 r90 bottom value=4.99k
R51 "CRCW060330K1FKEA" 0603 12090,16280 r90 bottom value=30.1k
R52 "CMP-0026505-2" 0402L 17007.28,16106.37 r270 top value=681
R53 "CMP-0025950-3" 0402L 17071.74,16142.9 r270 bottom value=100k
R54 "CRCW04021K00JNED" 0402L 17195,15870 r0 bottom value=1.0k
R55 "DNP" 0402L 17442.28,16286.37 r0 bottom value=4.99k
R56 "CMP-0026414-2" 0402L 17442.28,16274.56 r180 top value=4.99k
R57 "CMP-0025958-3" 0402L 17004.37,15860 r90 bottom value=10.0k
R58 "CMP-0026414-2" 0402L 17442.28,16321.37 r0 bottom value=4.99k
R59 "DNP" 0402L 17442.28,16309.56 r180 top value=4.99k
R60 "CRCW06030000Z0EA" 0603 17695,16768.89 r270 top value=0
R61 "CRCW06030000Z0EA" 0603 17760,16768.89 r270 top value=0
R62 "CRCW0603180KJNEA" 0603 12090,16620 r270 bottom value=180k
R63 "CRCW060330K1FKEA" 0603 12090,16483.5 r270 bottom value=30.1k
R64 "CRCW060330K1FKEA" 0603 13413.59,14890.39 r0 bottom value=30.1k
R66 "CRCW06030000Z0EA" 0603 18303.11,16004.8 r90 bottom value=0
R67 "CRCW06030000Z0EA" 0603 18240.55,16005.52 r90 bottom value=0
R68 "DNP" 0603 15470,16930 r0 bottom value=0
R69 "ERJ-8ENF60R4V" 1206 15300,16930 r0 bottom value=60.4
R70 "CRCW06030000Z0EA" 0603 18428.81,16444.05 r180 top value=0
R71 "CRCW06030000Z0EA" 0603 17989.63,16769.57 r270 top value=0
R72 "ERJ-8ENF60R4V" 1206 15300.36,16828.97 r180 bottom value=60.4
R73 "CRCW06032R21FKEA" 0603 13136.25,15490 r90 bottom value=2.21
R74 "CRCW06032R21FKEA" 0603 13191.25,15490 r270 bottom value=2.21
R75 "CRCW0402100KFKED" 0402S 13104.42,15411.01 r0 bottom value=100k
R76 "CRCW0402100KFKED" 0402S 13255,15425 r180 bottom value=100k
R77 "ULRB22512R0015FLFSLT" ULRB22512_085 12469.31,14507.75 r270 top value=0.0015
R78 "ULRB22512R0015FLFSLT" ULRB22512_085 13910,14505 r90 top value=0.0015
R79 "CRCW06030000Z0EA" 0603 18430,16506.46 r180 top value=0
R80 "DNP" 0603 15470.07,16863.68 r180 bottom value=0
R83 "CRCW06030000Z0EA" 0603 11895,14665 r270 top value=0
R84 "CRCW060310R0FKEA" 0603S 12855,15150 r90 bottom value=10.0
R85 "CRCW060310R0FKEA" 0603S 13350,15115 r180 bottom value=10.0
R86 "DNP" 1206L 13120,15230 r90 bottom value=3.24
R87 "CRCW06030000Z0EA" 0603 12911.67,14860.31 r180 bottom value=0
R88 "CRCW06030000Z0EA" 0603 12909.55,14923.01 r180 bottom value=0
R89 "CRCW06030000Z0EA" 0603 13408.65,14825.21 r0 bottom value=0
R90 "CRCW06030000Z0EA" 0603 13408.76,14765.39 r0 bottom value=0
R91 "DNP" 1206L 13284,15230 r90 bottom value=3.24
R92 "CRCW0402100KFKED" 0402S 12806.83,15160 r90 bottom value=100k
R93 "CRCW0402100KFKED" 0402S 13430,15160 r90 bottom value=100k
R94 "CRCW0603180KJNEA" 0603 13320.93,14899.9 r270 bottom value=180k
R96 "DNP" 0603S 13394.79,14697.8 r0 bottom value=0
R97 "CRCW06030000Z0EA" 0603 13095.63,14555 r90 bottom value=0
R98 "DNP" 0603S 13393.97,14651.78 r180 bottom value=0
R99 "CRCW0402100KFKED" 0402S 13396,14555 r270 bottom value=100k
R100 "CRCW06037K50FKEA" 0603 13654.98,14437.13 r180 bottom value=7.50k
R101 "DNP" 0603 13095.63,14555 r270 top value=0
R102 "CRCW06030000Z0EA" 0603 13620,14730 r270 top value=0
R103 "CRCW06030000Z0EA" 0603 13307.26,14555 r270 bottom value=0
R104 "DNP" 0402S 13355,14555 r270 bottom value=100k
R105 "CRCW06035K10JNEA" 0603 12980.63,14550 r270 top value=5.1k
R106 "CRCW06035K10JNEA" 0603 13654.98,14437.13 r180 top value=5.1k
R107 "CRCW060310K0FKEA" 0603 13254.26,14555 r90 bottom value=10.0k
R109 "CRCW06030000Z0EA" 0603 13690,14730 r90 top value=0
R110 "CRCW060313K0FKEA" 0603 13202.26,14555 r270 bottom value=13.0k
R111 "DNP" 0603S 12925.63,14560 r90 top value=75.0k
R112 "CRCW06032K20JNEA" 0603 12947.5,14437.77 r0 top value=2.2k
R113 "DNP" 0603 13660,14770 r180 bottom value=0
R114 "CRCW06030000Z0EA" 0603 13150.63,14555 r90 top value=0
R115 "DNP" 0603 13150.63,14555 r270 bottom value=0
R116 "ERA-3AEB622V" FP-ERA-3AEB622V_0603-MFG 13035.63,14550 r90 bottom value=6.2k
R118 "CRCW060347K5FKEA" 0603 13175,14430 r180 bottom value=47.5k
R119 "CRCW060320K0FKEA" 0603S 12805,14730 r90 bottom value=20.0k
R120 "CRCW060378K7FKEA" 0603 13525,14675 r90 bottom value=78.7k
R121 "CRCW0402100KFKED" 0402 17765,16365 r270 bottom value=100k
R122 "CRCW040247K0JNED" 0402 17716.08,16165.3 r180 bottom value=47k
R123 "CRCW06030000Z0EA" 0603 17760,12524.37 r270 top value=0
R124 "CRCW06030000Z0EA" 0603 18115,16005 r90 bottom value=0
R125 "DNP" 0603 17760,16768.89 r90 bottom value=0
R126 "CRCW040247K0JNED" 0402 18418.43,16264.22 r180 bottom value=47k
R127 "CRCW06030000Z0EA" 0603 18055,16005 r90 bottom value=0
R128 "CRCW06030000Z0EA" 0603 17830,12524.37 r270 top value=0
R130 "DNP" 0603 17695,16768.89 r90 bottom value=0
R132 "DNP" 0603 17823.6,16769.4 r90 bottom value=0
R133 "DNP" 0603 17885.55,16770.24 r90 bottom value=0
R134 "CRCW04022K20FKED" 0402 18418.35,16360.36 r0 bottom value=2.20k
R136 "CRCW04022K20FKED" 0402 18418.7,16312.98 r0 bottom value=2.20k
R137 "CRCW06030000Z0EA" 0603 17947.38,16768.84 r90 bottom value=0
R138 "CRCW06030000Z0EA" 0603 18131.58,16769.85 r90 bottom value=0
R140 "CRCW06030000Z0EA" 0603 18192.88,16770.68 r90 bottom value=0
R141 "CRCW06030000Z0EA" 0603 18254.16,16771.12 r90 bottom value=0
R142 "CRCW06030000Z0EA" 0603 18317.14,16771.12 r90 bottom value=0
R143 "CRCW06030000Z0EA" 0603 18375.34,16771.12 r90 bottom value=0
R144 "DNP" 0603 18436.35,16770.56 r90 bottom value=0
R145 "DNP" 0603 18430,16595 r0 bottom value=0
R146 "DNP" 0603 18430,16535 r0 bottom value=0
R147 "CRCW06030000Z0EA" 0603 18430,16475 r0 bottom value=0
R150 "CRCW06030000Z0EA" 0603 18430,16415 r0 bottom value=0
R151 "CRCW06030000Z0EA" 0603 18430.39,16207.27 r0 bottom value=0
R152 "CMP-0025958-3" 0402L 18055,16005 r90 top value=10.0k
R153 "CMP-0025958-3" 0402L 18115,16005 r90 top value=10.0k
R155 "CRCW060310K0FKEA" 0603 16232.77,15916.08 r0 top value=10.0k
R157 "CRCW06030000Z0EA" 0603 16900,16230.63 r90 bottom value=0
R158 "CRCW06030000Z0EA" 0603 16840,16230.63 r90 bottom value=0
R160 "CRCW060310K0FKEA" 0603 16376.88,15915.78 r0 top value=10.0k
R163 "CRCW060310K0FKEA" 0603 16534.88,15916.39 r0 top value=10.0k
R166 "CRCW06030000Z0EA" 0603 18008.33,16769.57 r270 bottom value=0
R167 "CRCW06030000Z0EA" 0603 18070.1,16769.85 r270 bottom value=0
R169 "CRCW060310K0FKEA" 0603 16677.81,15915.71 r0 top value=10.0k
R171 "CRCW04024K99FKED" 0402 16110,15910 r180 top value=4.99k
R172 "DNP" 0603 15730,15740 r90 top value=0
R173 "CRCW04024K99FKED" 0402 18250,15900 r180 top value=4.99k
RT3 "NCP18XH103D03RB" 0603S 12756.5,15248 r90 bottom value=10k
RT4 "NCP18XH103D03RB" 0603S 13625,15248 r90 bottom value=10k
S1 "1188E-1K2-V-TR" SW_1188E 17765,16030 r180 top
TP1 "TP_SM_1MM" TP_SM_1MM 15422.05,15690.55 r0 bottom
TP2 "TP_SM_1MM" TP_SM_1MM 15425,15759.45 r180 bottom
TP3 "TP_SM_1MM" TP_SM_1MM 15125,15405 r90 top
TP4 "TP_SM_1MM" TP_SM_1MM 15895,15345 r180 bottom
TP5 "TP_SM_1MM" TP_SM_1MM 15500,15150 r0 bottom
TP6 "TP_SM_1MM" TP_SM_1MM 15835,15390 r180 bottom
TP7 "TP_SM_1MM" TP_SM_1MM 15555,15130 r0 bottom
TP8 "TP_SM_1MM" TP_SM_1MM 15520.74,13508.15 r90 bottom
TP9 "TP_SM_1MM" TP_SM_1MM 15540,15305 r0 bottom
TP10 "TP_SM_1MM" TP_SM_1MM 15125,13508.15 r270 bottom
TP11 "TP_SM_1MM" TP_SM_1MM 15485.5,15228.5 r0 bottom
TP12 "TP_SM_1MM" TP_SM_1MM 15580,14935 r270 bottom
TP13 "TP_SM_1MM" TP_SM_1MM 15640,14935 r270 bottom
TP14 "TP_SM_1MM" TP_SM_1MM 15510.74,14150.15 r90 bottom
TP15 "TP_SM_1MM" TP_SM_1MM 15035,14590 r270 top
TP16 "TP_SM_1MM" TP_SM_1MM 15125,14150.15 r270 bottom
TP17 "TP_SM_1MM" TP_SM_1MM 15605,15155 r270 bottom
TP18 "TP_SM_1MM" TP_SM_1MM 15805,15190 r270 bottom
TP19 "TP_SM_1MM" TP_SM_1MM 15980,14870 r270 bottom
TP20 "TP_SM_1MM" TP_SM_1MM 16205.74,14150.15 r90 bottom
TP21 "TP_SM_1MM" TP_SM_1MM 15830,14615 r270 bottom
TP22 "TP_SM_1MM" TP_SM_1MM 15810,14150.15 r270 bottom
TP23 "TP_SM_1MM" TP_SM_1MM 15740,15180 r270 bottom
TP24 "TP_SM_1MM" TP_SM_1MM 15849,15230 r0 bottom
TP25 "TP_SM_1MM" TP_SM_1MM 15842,15305 r0 bottom
TP26 "TP_SM_1MM" TP_SM_1MM 16205.74,13508.15 r90 bottom
TP27 "TP_SM_1MM" TP_SM_1MM 16044,15078 r0 bottom
TP28 "TP_SM_1MM" TP_SM_1MM 15810,13508.15 r270 bottom
TP29 "TP_SM_1MM" TP_SM_1MM 15865,15175 r0 bottom
TP30 "TP_SM_1MM" TP_SM_1MM 17130,15735.94 r180 bottom
TP31 "TP_SM_1MM" TP_SM_1MM 17065,15670 r180 top
TP32 "TP_SM_1MM" TP_SM_1MM 16835,15505 r0 top
TP33 "TP_SM_1MM" TP_SM_1MM 17906.89,15410.63 r0 top
TP34 "TP_SM_1MM" TP_SM_1MM 17212.5,15141 r0 bottom
TP35 "TP_SM_1MM" TP_SM_1MM 17906.89,15495.63 r0 top
TP36 "TP_SM_1MM" TP_SM_1MM 17024.61,15053.26 r0 bottom
TP37 "TP_SM_1MM" TP_SM_1MM 17210.74,13508.15 r90 bottom
TP38 "TP_SM_1MM" TP_SM_1MM 17228.07,15301 r0 bottom
TP39 "TP_SM_1MM" TP_SM_1MM 16815,13508.15 r270 bottom
TP40 "TP_SM_1MM" TP_SM_1MM 17223.5,15226 r0 bottom
TP41 "TP_SM_1MM" TP_SM_1MM 17276.87,14919.37 r270 bottom
TP42 "TP_SM_1MM" TP_SM_1MM 17346.87,14919.37 r270 bottom
TP43 "TP_SM_1MM" TP_SM_1MM 17199.61,14131.19 r90 bottom
TP44 "TP_SM_1MM" TP_SM_1MM 17150,14850 r270 bottom
TP45 "TP_SM_1MM" TP_SM_1MM 16815,14150.15 r270 bottom
TP46 "TP_SM_1MM" TP_SM_1MM 17219.5,14877.5 r270 bottom
TP47 "TP_SM_1MM" TP_SM_1MM 17540.4,15092.1 r270 bottom
TP48 "TP_SM_1MM" TP_SM_1MM 17639.69,14953.51 r270 bottom
TP49 "TP_SM_1MM" TP_SM_1MM 17895.74,14150.15 r90 bottom
TP50 "TP_SM_1MM" TP_SM_1MM 17417.33,15145.47 r270 bottom
TP51 "TP_SM_1MM" TP_SM_1MM 17500,14150.15 r270 bottom
TP52 "TP_SM_1MM" TP_SM_1MM 17485,15170 r270 bottom
TP53 "TP_SM_1MM" TP_SM_1MM 17556.5,15231 r0 bottom
TP54 "TP_SM_1MM" TP_SM_1MM 17757.1,15292.83 r0 bottom
TP55 "TP_SM_1MM" TP_SM_1MM 17895.74,13508.15 r90 bottom
TP56 "TP_SM_1MM" TP_SM_1MM 17754.72,15066.39 r0 bottom
TP57 "TP_SM_1MM" TP_SM_1MM 17500,13508.15 r270 bottom
TP58 "TP_SM_1MM" TP_SM_1MM 17555,15165 r0 bottom
TP59 "TP_SM_1MM" TP_SM_1MM 13025,13525 r180 top
TP60 "TP_SM_1MM" TP_SM_1MM 11805,14180 r180 top
TP68 "TP_SM_1MM" TP_SM_1MM 13807.44,16745 r90 top
TP69 "TP_SM_1MM" TP_SM_1MM 14022.44,16745 r90 top
TP71 "TP_SM_1MM" TP_SM_1MM 13805,16850 r90 top
TP72 "TP_SM_1MM" TP_SM_1MM 14265,16745 r90 top
TP73 "TP_SM_1MM" TP_SM_1MM 11935,16105 r0 top
TP74 "TP_SM_1MM" TP_SM_1MM 12380,15990 r90 bottom
TP75 "TP_SM_1MM" TP_SM_1MM 12175,16115 r90 top
TP76 "TP_SM_1MM" TP_SM_1MM 11955,14320 r270 top
TP77 "TP_SM_1MM" TP_SM_1MM 11945,14435 r270 top
TP78 "TP_SM_1MM" TP_SM_1MM 14419.37,16098.46 r270 bottom
TP79 "TP_SM_1MM" TP_SM_1MM 12222.29,15692.2 r180 bottom
TP80 "TP_SM_1MM" TP_SM_1MM 14120,15620 r0 bottom
TP81 "TP_SM_1MM" TP_SM_1MM 15104.11,16098.46 r270 bottom
TP82 "TP_SM_1MM" TP_SM_1MM 15709.72,15914.72 r0 bottom
TP83 "TP_SM_1MM" TP_SM_1MM 13435,14450 r90 bottom
TP84 "TP_SM_1MM" TP_SM_1MM 13280,14430 r0 top
U1 "TAS6684QPHDRQ1" PHD0064B-MFG 15682.52,15295.63 r270 top locked
U2 "TAS6684QPHDRQ1" PHD0064B-MFG 17387.52,15295.63 r270 top locked
U3 "LM74700QDBVTQ1" DBV0006A_N 12355,13775 r180 top
U4 "LM1117IDT-3.3/NOPB" NDP0003B_N 13225,16765 r0 bottom
U5 "LMQ66430MC3RXBRQ1" RXB0014A-MFG 12590,16765 r0 top
U6 "CMP-0004896-1" PLR135_T10 18190,12285 r180 top
U7 "TI-DIR9001-Q1-TSSOP_PW-28" PW0028A_N 17217.28,16091.37 r180 top
U8 "LM5125QRHBRQ1" RHB0032U-MFG 13163.16,14795.63 r0 bottom
U9 "SN74AHC1G00QDCKRQ1" DCK0005A_N 13650,14557.52 r270 top
U10 "MSPM0G3507QPMQ1" PM0064A-MFG 18076.78,16345.78 r180 bottom
U11 "LMK1C1102PWR" PW0008A-MFG 16231.61,16100.83 r270 top
U12 "LMK1C1102PWR" PW0008A-MFG 16383.39,16100.83 r270 top
U13 "LMK1C1102PWR" PW0008A-MFG 16533.39,16100.83 r270 top
U14 "LMK1C1102PWR" PW0008A-MFG 16685,16100 r270 top
U15 "LM1117IDT-5.0/NOPB" NDP0003B 14680.04,16790 r0 top
U16 "TCAN1044VDRQ1" D0008A-MFG 15297.88,16838.35 r0 top
Y1 "ABM10-24.576MHZ-E20-T" XTAL_ABM10 17492.52,16064.61 r0 top
Y2 "X1A0001410014" Epson_FC-135 17690,16435 r270 bottom
Y3 "X1E0000210179" FP-X1E0000210179_TSX-3225-MFG 17725,16590 r180 bottom

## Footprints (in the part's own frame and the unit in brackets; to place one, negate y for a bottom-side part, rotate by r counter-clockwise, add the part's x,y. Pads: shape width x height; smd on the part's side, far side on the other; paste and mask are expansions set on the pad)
0201_033 [mm] "SMD, 2-Leads, Height 0.33mm"
  rect 0.46x0.42 smd mask+0.048: 1(-0.33,0) 2(0.33,0)
  body extent -0.31,-0.16 0.31,0.16, height 0.33
0402 [mm] "0402 from SM-752 data"
  rect 0.8x0.6 smd: 1(-0.6,0) 2(0.6,0)
  silkscreen extent -1.22,-0.52 1.22,0.52, body extent -0.55,-0.3 0.55,0.3, height 0.6
0402L [mm] "0402 from SM-752 data"
  rect 0.6x0.5 smd: 1(-0.5,0) 2(0.5,0)
  body extent -0.55,-0.3 0.55,0.3, height 0.6
0402S [mil] "Based on C0402S footprint from PADS legacy"
  rect 15x24 smd: 1(-20,0) 2(20,0)
  body extent -22,-12 22,12, height 24
0603 [mm] "0603 from SM-752 data"
  rect 1x0.95 smd: 1(-0.8,0) 2(0.8,0)
  silkscreen extent -1.52,-0.69 1.52,0.69, body extent -0.87,-0.47 0.87,0.47, height 1
0603S [mil]
  rect 20x35 smd: 1(-30,0) 2(30,0)
  body extent -34,-19 34,19, height 39
0805_HV [mil] "0805 with 30mil clearance between pads"
  rect 50x63 smd: 1(-40,0) 2(40,0)
  silkscreen extent -74,-40 74,40, body extent -43,-29 43,29, height 57
1206 [mm] "1206 from SM-752 data"
  rect 1.3x1.85 smd: 1(-1.45,0) 2(1.45,0)
  silkscreen extent -2.4,-1.21 2.4,1.21, body extent -1.7,-0.9 1.7,0.9, height 1.35
1206L [mm] "1206 from SM-752 data"
  rect 1.1x1.75 smd: 1(-1.35,0) 2(1.35,0)
  silkscreen extent -0.4,-0.77 0.4,0.77, body extent -1.7,-0.9 1.7,0.9, height 1.35
1210 [mm] "1210 from SM-752 data"
  rect 1.3x2.7 smd: 1(-1.45,0) 2(1.45,0)
  silkscreen extent -2.32,-1.57 2.32,1.57, body extent -1.7,-1.35 1.7,1.35, height 1.35
1210_250 [mm] "1210"
  rect 1.3x2.7 smd: 1(-1.45,0) 2(1.45,0)
  silkscreen extent -2.32,-1.57 2.32,1.57, body extent -1.7,-1.35 1.7,1.35, height 2.5
1210_270 [mm] "1210"
  rect 1.3x2.7 smd: 1(-1.45,0) 2(1.45,0)
  silkscreen extent -2.32,-1.57 2.32,1.57, body extent -1.7,-1.35 1.7,1.35, height 2.7
1210_280 [mm] "SMD, 2-Leads, Body 3.6x2.8mm, Height 2.8mm"
  rect 1.1x2.2 smd: 1(-1.65,0) 2(1.65,0)
  silkscreen extent -0.84,-1.4 0.84,1.4, body extent -1.8,-1.4 1.8,1.4, height 2.8
ACT45B [mm] "SMD, 4-Leads, Body 4.7 x 3.7 mm"
  rect 1.35x0.9 smd: 1(-2.275,1.25) 2(-2.275,-1.25) 3(2.275,-1.25) 4(2.275,1.25)
  silkscreen extent -2.35,-1.7 2.35,2, body extent -2.35,-1.7 2.35,1.7, height 3
CE_Mark_5mm [mil] "Minimum text height for CE Mark"
  silkscreen extent -138,-98 138,98
D0008A-MFG [mm]
  rrect17% 1.55x0.6 smd paste+0 mask+0: 1(-2.7,1.905) 2(-2.7,0.635) 3(-2.7,-0.635) 4(-2.7,-1.905) 5(2.7,-1.905) 6(2.7,-0.635) 7(2.7,0.635) 8(2.7,1.905)
  silkscreen extent -4.17,-2.5 1.5,2.5, body extent -3.57,-2.75 3.57,2.75, height 0.25
DBV0006A_N [mm] "SOT23, 6-Leads, Body 2.9x1.6mm, Pitch 0.95mm, Lead Span 2.8mm, IPC Medium Density"
  rrect17% 1x0.6 smd: 1(-1.375,0.95) 2(-1.375,0) 3(-1.375,-0.95) 4(1.375,-0.95) 5(1.375,0) 6(1.375,0.95)
  silkscreen extent -1.68,-1.55 0.5,1.55, body extent -1.42,-1.46 1.42,1.46, height 1.12
DCK0005A_N [mm] "SOT353, 5-Leads, Body 2x1.3mm, Pitch 0.65mm, Lead Span 2.1mm, IPC Medium Density"
  rrect25% 0.85x0.4 smd: 1(-1.125,0.65) 2(-1.125,0) 3(-1.125,-0.65) 4(1.125,-0.65) 5(1.125,0.65)
  silkscreen extent -0.15,-1.1 0.15,1.1, body extent -1.14,-1 1.14,1, height 0.95
DNK0008A [mm] "SON, 8-Leads, Body 5x6mm"
  rrect39% 0.86x0.51 smd paste-0.05 mask-0.05: 1(-2.82,1.905) 2(-2.82,0.635) 3(-2.82,-0.635) 4(-2.82,-1.905) 5(2.82,-1.905) 6(2.82,-0.635) 7(2.82,0.635) 8(2.82,1.905)
  rrect8% 1.48x1.27 on Top Paste: 9(-0.18,1.47) 9(-0.18,0) 9(-0.18,-1.47) 9(1.5,-1.47) 9(1.5,0) 9(1.5,1.47)
  rrect5% 4.34x4.6 smd paste-3 mask-0.05: 9(1.08,0)
  silkscreen extent -3.2,-2.7 3.2,2.7, body extent -3.05,-2.55 3.05,2.55, height 1.06
Epson_FC-135 [mm] "SMD, 2-Leads, Body 3.2x1.5mm"
  rect 1x1.8 smd: 1(-1.25,0) 2(1.25,0)
  silkscreen extent -0.35,-0.8 0.35,0.8, body extent -1.65,-0.8 1.65,0.8, height 0.9
FCC_disclaimer_stacked [mil]
FP-1736713_HDR8-MFG [mm]
  rrect5% 2.15x2.15 hole 1.4 paste-2539.97 mask+0: 1(-7.62,9)
  round 2.15 hole 1.4 paste-2539.97 mask+0: 2(-7.62,-1.16) 3(-2.54,9) 4(-2.54,-1.16) 5(2.54,9) 6(2.54,-1.16) 7(7.62,9) 8(7.62,-1.16)
  silkscreen extent -11.76,-11.1 11.04,11.1, body extent -11.14,-11.2 11.14,11.2, height 0.25
FP-1762457_HDR20-MFG [mm]
  rrect5% 2.15x2.15 hole 1.4 paste-2539.97 mask+0: 1(-22.86,9)
  round 2.15 hole 1.4 paste-2539.97 mask+0: 2(-22.86,-1.16) 3(-17.78,9) 4(-17.78,-1.16) 5(-12.7,9) 6(-12.7,-1.16) 7(-7.62,9) 8(-7.62,-1.16) 9(-2.54,9) 10(-2.54,-1.16) 11(2.54,9) 12(2.54,-1.16) 13(7.62,9) 14(7.62,-1.16) 15(12.7,9) 16(12.7,-1.16) 17(17.78,9) 18(17.78,-1.16) 19(22.86,9) 20(22.86,-1.16)
  body extent -26.4,-11.2 26.4,11.2, height 0.25
FP-ERA-3AEB622V_0603-MFG [mm]
  rrect15% 0.65x0.9 smd paste+0 mask+0: 1(-0.725,0) 2(0.725,0)
  silkscreen extent 0,-0.5 0,0.5, body extent -0.8,-0.4 0.8,0.4, height 0.55
FP-GCJ188R71H473KA12D_0603-MFG [mm]
  rrect15% 0.65x0.7 smd paste+0 mask+0: 1(-0.675,0) 2(0.675,0)
  silkscreen extent -0.9,-0.72 0.9,0.72, body extent -0.8,-0.4 0.8,0.4, height 0.9
FP-GCM155-0_05-IPC_B [mil]
  rect 24.23x22.54 smd paste+0 mask+0: 1(-16.87,0) 2(16.87,0)
  silkscreen extent -29,-27 29,27, body extent -20,-10 20,10, height 22
FP-QTE-040-01-L-D-A_HDR80-MFG [mm]
  rrect22% 0.46x1.45 smd paste+0 mask+0: 1(-17.6,3.085) 2(-17.6,-3.085) 3(-16.8,3.085) 4(-16.8,-3.085) 5(-16,3.085) 6(-16,-3.085) 7(-15.2,3.085) 8(-15.2,-3.085) 9(-14.4,3.085) 10(-14.4,-3.085) 11(-13.6,3.085) 12(-13.6,-3.085) 13(-12.8,3.085) 14(-12.8,-3.085) 15(-12,3.085) 16(-12,-3.085) 17(-11.2,3.085) 18(-11.2,-3.085) 19(-10.4,3.085) 20(-10.4,-3.085) 21(-9.6,3.085) 22(-9.6,-3.085) 23(-8.8,3.085) 24(-8.8,-3.085) 25(-8,3.085) 26(-8,-3.085) 27(-7.2,3.085) 28(-7.2,-3.085) 29(-6.4,3.085) 30(-6.4,-3.085) 31(-5.6,3.085) 32(-5.6,-3.085) 33(-4.8,3.085) 34(-4.8,-3.085) 35(-4,3.085) 36(-4,-3.085) 37(-3.2,3.085) 38(-3.2,-3.085) 39(-2.4,3.085) 40(-2.4,-3.085) 41(2.4,3.085) 42(2.4,-3.085) 43(3.2,3.085) 44(3.2,-3.085) 45(4,3.085) 46(4,-3.085) 47(4.8,3.085) 48(4.8,-3.085) 49(5.6,3.085) 50(5.6,-3.085) 51(6.4,3.085) 52(6.4,-3.085) 53(7.2,3.085) 54(7.2,-3.085) 55(8,3.085) 56(8,-3.085) 57(8.8,3.085) 58(8.8,-3.085) 59(9.6,3.085) 60(9.6,-3.085) 61(10.4,3.085) 62(10.4,-3.085) 63(11.2,3.085) 64(11.2,-3.085) 65(12,3.085) 66(12,-3.085) 67(12.8,3.085) 68(12.8,-3.085) 69(13.6,3.085) 70(13.6,-3.085) 71(14.4,3.085) 72(14.4,-3.085) 73(15.2,3.085) 74(15.2,-3.085) 75(16,3.085) 76(16,-3.085) 77(16.8,3.085) 78(16.8,-3.085) 79(17.6,3.085) 80(17.6,-3.085)
  rrect16% 2.54x0.64 smd paste+0 mask+0: P1(-18.45,0) P1(-1.56,0) P2(1.55,0) P2(18.44,0)
  rrect16% 4.7x0.64 smd paste+0 mask+0: P1(-13.18,0) P1(-6.83,0) P2(6.82,0) P2(13.17,0)
  round 1.02 hole 1.02 unplated paste-2539.97 mask+0: ""(-19.24,2.035) ""(19.24,2.035)
  silkscreen extent -20.07,-3.01 20.07,4.51, body extent -20,-3.56 20,3.56, height 4.35
FP-VAMV1009AA-100MM2_SMT_CMC_9MM2_10MM2-MFG [mm]
  rrect4% 4.05x2.85 smd paste+0 mask+0: 1(-3.945,2.475) 2(-3.945,-2.475) 3(3.945,-2.475) 4(3.945,2.475)
  silkscreen extent -6.65,-5.2 4.7,5.2, body extent -6.07,-5.3 6.07,5.3, height 0.25
FP-VCMV136E-3R3MN2_SMT_IND_13MM45_12MM6-MFG [mm]
  rrect2% 4.335x5.7 smd paste+0 mask+0: 1(-5.768,0) 2(5.767,0)
  silkscreen extent -8.62,-6.4 6.9,6.4, body extent -8.04,-6.5 8.03,6.5, height 0.25
FP-X1E0000210179_TSX-3225-MFG [mm]
  rrect9% 1.4x1.15 smd paste+0 mask+0: 1(-1.1,-0.8) 2(1.1,-0.8) 3(1.1,0.8) 4(-1.1,0.8)
  silkscreen extent -1.23,-2.05 0,1.33, body extent -1.6,-1.25 1.6,1.25, height 0.6
FP-XEL4030-222MEC_SMT2_4MM0_4MM0-MFG [mm]
  rrect10% 0.98x3.4 smd paste+0 mask+0: 1(-1.185,0) 2(1.185,0)
  silkscreen extent -2.77,-2.15 2.15,2.15, body extent -2.25,-2.25 2.25,2.25, height 0.25
HARWIN_S1911-46R [mm] "HARWIN"
  rect 2.48x3 smd mask+0.102: 1(-2.69,0) 2(2.69,0)
  silkscreen extent -0.5,-1.5 0.5,1.5, body extent -3.42,-1.25 3.43,1.26, height 0.99
LED_LTST-C170_Red [mm] "LITE-ON"
  rect 1.2x1.2 smd: 1(-1.05,0) 2(1.05,0)
  silkscreen extent -1.6,-1 2.2,1, body extent -1.05,-0.67 1.05,0.67, height 1.1
LED_SMLP12_BLUE [mm] "Rohm Semiconductor"
  rect 0.5x0.6 smd mask+0.08: 1(-0.45,0) 2(0.45,0)
  silkscreen extent 0.92,-0.3 0.92,0.3, body extent -0.55,-0.35 0.55,0.35, height 0.25
LTST-C170KGKT_Green [mm] "LITE-ON"
  rect 1.2x1.2 smd: 1(-1.05,0) 2(1.05,0)
  silkscreen extent -1.6,-1 2.2,1, body extent -1.05,-0.67 1.05,0.67, height 1.1
NDP0003B [mm] "TO-252-3"
  rrect8% 2.15x1.3 smd: 1(-4.38,2.285) 3(-4.38,-2.285)
  rrect2% 5.7x5.5 smd paste-3: 4(2.285,0)
  body extent -4.95,-3.29 4.96,3.29, height 2.48
NDP0003B_N [mm] "D-PAK, 4-Leads, Body 6.1x6.6mm, Pitch 2.29mm, Lead Span 9.7mm, IPC Medium Density"
  rrect11% 1.9x0.95 smd: 1(-4.35,2.28) 3(-4.35,-2.28)
  rrect2% 6.9x5.5 smd: 4(1.85,0)
  silkscreen extent -4.47,-3.35 -2,3.43, body extent -2.5,-3.35 3.7,3.35, height 2.38
Net-Tie_10milWide_30milLong [mil] "10mil net tie, no solder mask opening, no solder paste"
  rect 30x10 smd paste-5 mask-5: 1(-15,0) 2(15,0)
Nichicon_1000x1000 [mm] "SMD, 2-Leads, Dia 10mm"
  rrect4% 4x2.5 smd: 1(-4,0) 2(4,0)
  silkscreen extent -5.25,-5.25 5.25,5.25, body extent -5.25,-5.25 5.25,5.25, height 10.81
Panasonic_B [mm] "SMD, 2-Leads, Dia 4mm"
  rrect6% 2.5x1.6 smd: 1(-1.75,0) 2(1.75,0)
  silkscreen extent -2,-2.15 2.15,2.15, body extent -2.15,-2.15 2.15,2.15, height 6.1
PBC03SAAN [mm] "Sullins 100mil, 1x3, 230 mil above insulator"
  rect 1.65x1.65 hole 1.016: 1(-2.54,0)
  round 1.65 hole 1.016: 2(0,0) 3(2.54,0)
  silkscreen extent -3.81,-1.27 3.81,1.27, body extent -3.81,-1.27 3.81,1.27, height 8.38
PHD0064B-MFG [mm]
  rrect18% 1.5x0.55 smd paste+0 mask+0: 1(-7.7,6) 2(-7.7,5.2) 3(-7.7,4.4) 4(-7.7,3.6) 5(-7.7,2.8) 6(-7.7,2) 7(-7.7,1.2) 8(-7.7,0.4) 9(-7.7,-0.4) 10(-7.7,-1.2) 11(-7.7,-2) 12(-7.7,-2.8) 13(-7.7,-3.6) 14(-7.7,-4.4) 15(-7.7,-5.2) 16(-7.7,-6) 33(7.7,-6) 34(7.7,-5.2) 35(7.7,-4.4) 36(7.7,-3.6) 37(7.7,-2.8) 38(7.7,-2) 39(7.7,-1.2) 40(7.7,-0.4) 41(7.7,0.4) 42(7.7,1.2) 43(7.7,2) 44(7.7,2.8) 45(7.7,3.6) 46(7.7,4.4) 47(7.7,5.2) 48(7.7,6)
  rrect18% 0.55x1.5 smd paste+0 mask+0: 17(-6,-7.7) 18(-5.2,-7.7) 19(-4.4,-7.7) 20(-3.6,-7.7) 21(-2.8,-7.7) 22(-2,-7.7) 23(-1.2,-7.7) 24(-0.4,-7.7) 25(0.4,-7.7) 26(1.2,-7.7) 27(2,-7.7) 28(2.8,-7.7) 29(3.6,-7.7) 30(4.4,-7.7) 31(5.2,-7.7) 32(6,-7.7) 49(6,7.7) 50(5.2,7.7) 51(4.4,7.7) 52(3.6,7.7) 53(2.8,7.7) 54(2,7.7) 55(1.2,7.7) 56(0.4,7.7) 57(-0.4,7.7) 58(-1.2,7.7) 59(-2,7.7) 60(-2.8,7.7) 61(-3.6,7.7) 62(-4.4,7.7) 63(-5.2,7.7) 64(-6,7.7)
  silkscreen extent -9.17,-6 6,6.13, body extent -8.55,-8.55 8.55,8.55, height 0.25
PLR135_T10 [mm] "EVERLIGHT"
  rect 1.45x1.45 hole 0.813: 1(2.54,-4.67)
  round 1.45 hole 0.813: 2(0,-4.67) 3(-2.54,-4.67)
  round 1.75 hole 1.092: 4(2.54,-2.13) 5(-2.54,-2.04)
  silkscreen extent -5.05,-6.93 5.05,6.95, body extent -5,-6.9 5,6.9, height 10.3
